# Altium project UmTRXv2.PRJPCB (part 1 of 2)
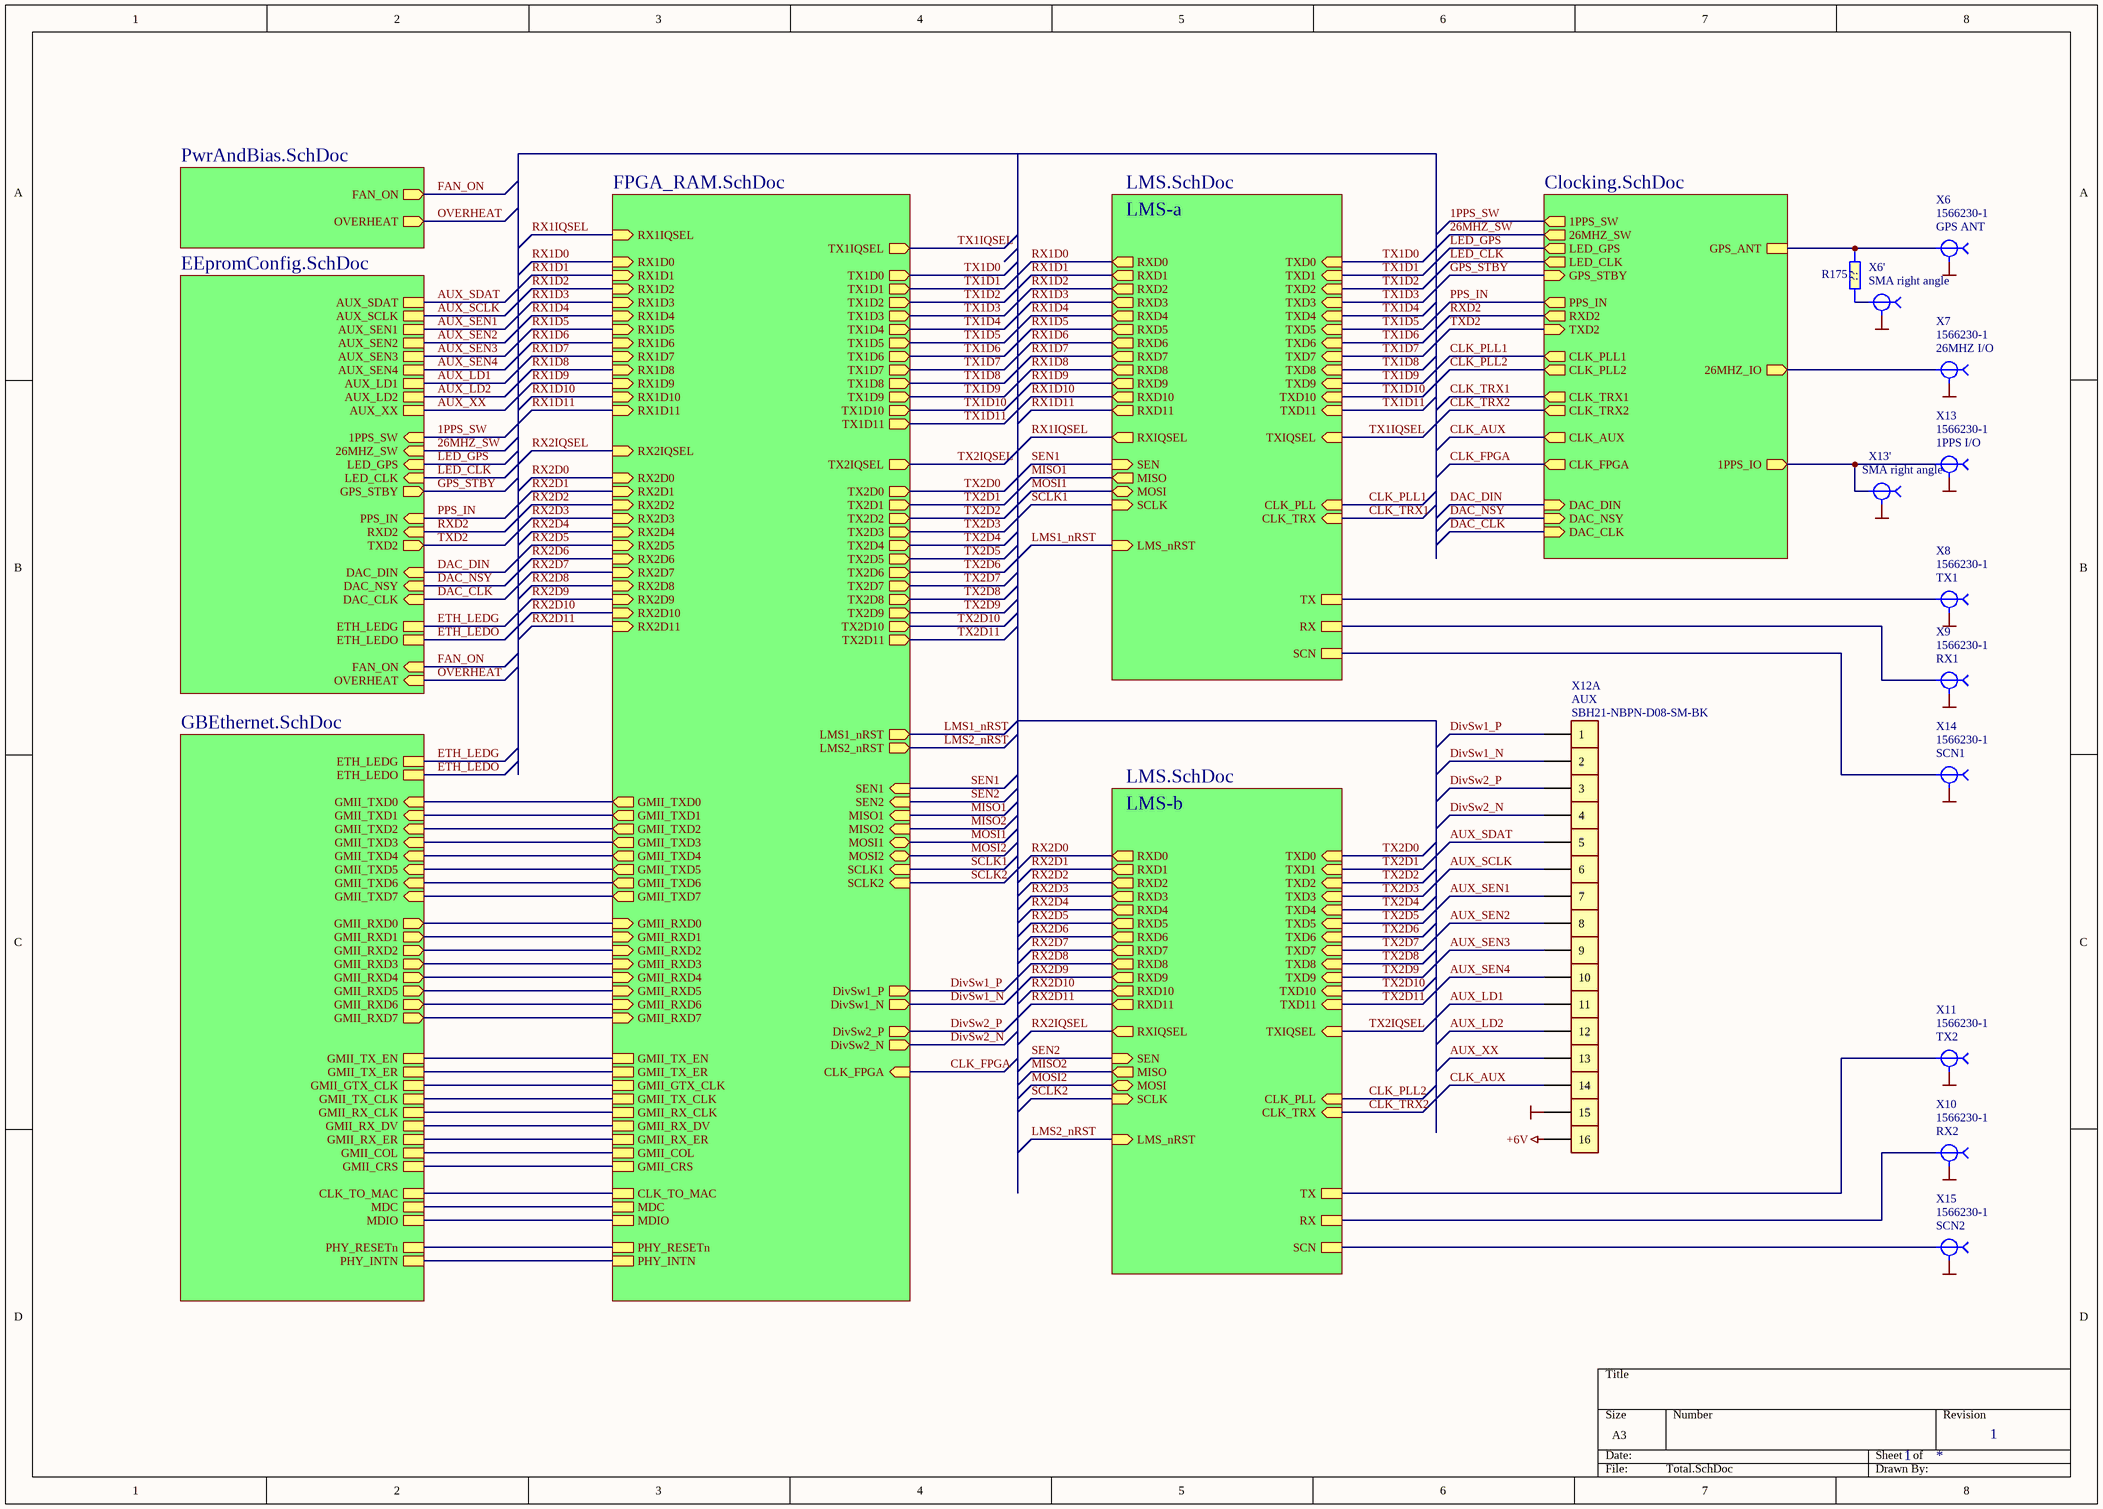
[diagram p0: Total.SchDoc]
7 sheets, 708 parts. Net scope: hierarchical (ports join the sheet entries above them; power ports are global).
Board file: UmTRXv2.PcbDoc
Sheets:
  Total.SchDoc
    PwrAndBias = PwrAndBias.SchDoc
    FPGA_RAM = FPGA_RAM.SchDoc
    GBEthernet = GBEthernet.SchDoc
    EEpromConfig = EEpromConfig.SchDoc
    Clocking = Clocking.SchDoc
    LMS-a = LMS.SchDoc
    LMS-b = LMS.SchDoc

## Sheet Total.SchDoc: USRP Cellular Tranceiver
size A3; Revision: 1; SheetNumber: 1

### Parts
R175  ??  [R0603-PHILLIPS]
X6  1566230-1  Dscription: GPS ANT  [U_FL]
X6'  SMA right angle  [SMA right angle]
X7  1566230-1  Dscription: 26MHZ I/O  [U_FL]
X8  1566230-1  Dscription: TX1  [U_FL]
X9  1566230-1  Dscription: RX1  [U_FL]
X10  1566230-1  Dscription: RX2  [U_FL]
X11  1566230-1  Dscription: TX2  [U_FL]
X12  SBH21-NBPN-D08-SM-BK  Misc: AUX  [SBH-16]  (parts A,B,C,D,E,F,G,H,I,J,K,L,M,N,O,P of 16)
X13  1566230-1  Dscription: 1PPS I/O  [U_FL]
X13'  SMA right angle  [SMA right angle]
X14  1566230-1  Dscription: SCN1  [U_FL]
X15  1566230-1  Dscription: SCN2  [U_FL]

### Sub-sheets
Clocking = Clocking.SchDoc: TXD2 (in), 26MHZ_IO (out), CLK_FPGA (out), CLK_TRX1 (out), GPS_ANT, DAC_DIN (in), DAC_NSY (in), DAC_CLK (in), PPS_IN (out), RXD2 (out), CLK_PLL1 (out), CLK_AUX (out), 1PPS_IO (out), CLK_PLL2 (out), CLK_TRX2 (out), 1PPS_SW (out), 26MHZ_SW (out), LED_GPS (out), LED_CLK (out), GPS_STBY (in)
EEpromConfig = EEpromConfig.SchDoc: PPS_IN (in), DAC_DIN (in), DAC_NSY (in), DAC_CLK (in), TXD2 (out), RXD2 (in), ETH_LEDG, ETH_LEDO, FAN_ON (in), OVERHEAT (in), AUX_SDAT, AUX_SCLK, AUX_SEN1, AUX_LD1, AUX_XX, AUX_SEN2, AUX_LD2, 1PPS_SW (in), 26MHZ_SW (in), LED_GPS (in), LED_CLK (in), AUX_SEN3, AUX_SEN4, GPS_STBY (out)
FPGA_RAM = FPGA_RAM.SchDoc: DivSw1_P (out), DivSw1_N (out), TX1IQSEL (out), TX2IQSEL (out), RX1IQSEL (in), RX2IQSEL (in), SEN1 (in), SEN2 (in), MISO1 (in), MOSI1 (bidir), SCLK1 (in), DivSw2_P (out), DivSw2_N (out), CLK_FPGA (in), CLK_TO_MAC, GMII_TX_EN, GMII_TX_ER, GMII_GTX_CLK, GMII_TX_CLK, GMII_RX_CLK, GMII_RX_DV, GMII_RX_ER, GMII_COL, GMII_CRS, MDIO, MDC, PHY_INTN, PHY_RESETn, MISO2 (in), MOSI2 (bidir), SCLK2 (in), LMS1_nRST (out), LMS2_nRST (out), TX1D0 (out), TX1D1 (out), TX1D2 (out), TX1D3 (out), TX1D4 (out), TX1D5 (out), TX1D6 (out), TX1D7 (out), TX1D8 (out), TX1D9 (out), TX1D10 (out), TX1D11 (out), TX2D0 (out), TX2D1 (out), TX2D2 (out), TX2D3 (out), TX2D4 (out), TX2D5 (out), TX2D6 (out), TX2D7 (out), TX2D8 (out), TX2D9 (out), TX2D10 (out), TX2D11 (out), RX1D0 (in), RX1D1 (in), RX1D2 (in), RX1D3 (in), RX1D4 (in), RX1D5 (in), RX1D6 (in), RX1D7 (in), RX1D8 (in), RX1D9 (in), RX1D10 (in), RX1D11 (in), RX2D0 (in), RX2D1 (in), RX2D2 (in), RX2D3 (in), RX2D4 (in), RX2D5 (in), RX2D6 (in), RX2D7 (in), RX2D8 (in), RX2D9 (in), RX2D10 (in), RX2D11 (in), GMII_TXD0 (out), GMII_TXD1 (out), GMII_TXD2 (out), GMII_TXD3 (out), GMII_TXD4 (out), GMII_TXD5 (out), GMII_TXD6 (out), GMII_TXD7 (out), GMII_RXD0 (in), GMII_RXD1 (in), GMII_RXD2 (in), GMII_RXD3 (in), GMII_RXD4 (in), GMII_RXD5 (in), GMII_RXD6 (in), GMII_RXD7 (in)
GBEthernet = GBEthernet.SchDoc: CLK_TO_MAC, GMII_TX_ER, GMII_TX_EN, GMII_GTX_CLK, GMII_RX_CLK, GMII_TX_CLK, GMII_RX_DV, GMII_RX_ER, GMII_COL, GMII_CRS, MDC, MDIO, PHY_INTN, PHY_RESETn, ETH_LEDG, GMII_TXD0 (in), GMII_TXD1 (in), GMII_TXD2 (in), GMII_TXD3 (in), GMII_TXD4 (in), GMII_TXD5 (in), GMII_TXD6 (in), GMII_TXD7 (in), GMII_RXD0 (out), GMII_RXD1 (out), GMII_RXD2 (out), GMII_RXD3 (out), GMII_RXD4 (out), GMII_RXD5 (out), GMII_RXD6 (out), GMII_RXD7 (out), ETH_LEDO
LMS-a = LMS.SchDoc: RXD0 (out), RXIQSEL (out), SEN (in), MISO (out), MOSI (bidir), SCLK (in), RXD1 (out), RXD2 (out), RXD3 (out), RXD4 (out), RXD5 (out), RXD6 (out), RXD7 (out), RXD8 (out), RXD9 (out), RXD10 (out), RXD11 (out), TXD0 (in), TXIQSEL (in), CLK_PLL (in), TXD1 (in), TXD2 (in), TXD3 (in), TXD4 (in), TXD5 (in), TXD6 (in), TXD7 (in), TXD8 (in), TXD9 (in), TXD10 (in), TXD11 (in), TX, RX, LMS_nRST (in), SCN, CLK_TRX (in)
LMS-b = LMS.SchDoc: RXD0 (out), RXIQSEL (out), SEN (in), MISO (out), MOSI (bidir), SCLK (in), RXD1 (out), RXD2 (out), RXD3 (out), RXD4 (out), RXD5 (out), RXD6 (out), RXD7 (out), RXD8 (out), RXD9 (out), RXD10 (out), RXD11 (out), TXD0 (in), TXIQSEL (in), CLK_PLL (in), TXD1 (in), TXD2 (in), TXD3 (in), TXD4 (in), TXD5 (in), TXD6 (in), TXD7 (in), TXD8 (in), TXD9 (in), TXD10 (in), TXD11 (in), TX, RX, LMS_nRST (in), CLK_TRX (in), SCN
PwrAndBias = PwrAndBias.SchDoc: FAN_ON (out), OVERHEAT (out)

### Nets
+6V: X12.16
GND: X6.2(GND) X6'.2(GND) X7.2(GND) X8.2(GND) X9.2(GND) X10.2(GND) X11.2(GND) X12.15 X13.2(GND) X13'.2(GND) X14.2(GND) X15.2(GND)
1PPS_IO: X13.1 X13'.1 ; sheet Clocking/1PPS_IO
1PPS_SW: sheet EEpromConfig/1PPS_SW, sheet Clocking/1PPS_SW
26MHZ_IO: X7.1 ; sheet Clocking/26MHZ_IO
26MHZ_SW: sheet EEpromConfig/26MHZ_SW, sheet Clocking/26MHZ_SW
AUX_LD1: X12.11 ; sheet EEpromConfig/AUX_LD1
AUX_LD2: X12.12 ; sheet EEpromConfig/AUX_LD2
AUX_SCLK: X12.6 ; sheet EEpromConfig/AUX_SCLK
AUX_SDAT: X12.5 ; sheet EEpromConfig/AUX_SDAT
AUX_SEN1: X12.7 ; sheet EEpromConfig/AUX_SEN1
AUX_SEN2: X12.8 ; sheet EEpromConfig/AUX_SEN2
AUX_SEN3: X12.9 ; sheet EEpromConfig/AUX_SEN3
AUX_SEN4: X12.10 ; sheet EEpromConfig/AUX_SEN4
AUX_XX: X12.13 ; sheet EEpromConfig/AUX_XX
CLK_AUX: X12.14 ; sheet Clocking/CLK_AUX
CLK_FPGA: sheet FPGA_RAM/CLK_FPGA, sheet Clocking/CLK_FPGA
CLK_PLL1: sheet Clocking/CLK_PLL1, sheet LMS-a/CLK_PLL
CLK_PLL2: sheet Clocking/CLK_PLL2, sheet LMS-b/CLK_PLL
CLK_TO_MAC: sheet FPGA_RAM/CLK_TO_MAC, sheet GBEthernet/CLK_TO_MAC
CLK_TRX1: sheet Clocking/CLK_TRX1, sheet LMS-a/CLK_TRX
CLK_TRX2: sheet Clocking/CLK_TRX2, sheet LMS-b/CLK_TRX
DAC_CLK: sheet EEpromConfig/DAC_CLK, sheet Clocking/DAC_CLK
DAC_DIN: sheet EEpromConfig/DAC_DIN, sheet Clocking/DAC_DIN
DAC_NSY: sheet EEpromConfig/DAC_NSY, sheet Clocking/DAC_NSY
DivSw1_N: X12.2 ; sheet FPGA_RAM/DivSw1_N
DivSw1_P: X12.1 ; sheet FPGA_RAM/DivSw1_P
DivSw2_N: X12.4 ; sheet FPGA_RAM/DivSw2_N
DivSw2_P: X12.3 ; sheet FPGA_RAM/DivSw2_P
ETH_LEDG: sheet GBEthernet/ETH_LEDG, sheet EEpromConfig/ETH_LEDG
ETH_LEDO: sheet GBEthernet/ETH_LEDO, sheet EEpromConfig/ETH_LEDO
FAN_ON: sheet PwrAndBias/FAN_ON, sheet EEpromConfig/FAN_ON
GMII_COL: sheet FPGA_RAM/GMII_COL, sheet GBEthernet/GMII_COL
GMII_CRS: sheet FPGA_RAM/GMII_CRS, sheet GBEthernet/GMII_CRS
GMII_GTX_CLK: sheet FPGA_RAM/GMII_GTX_CLK, sheet GBEthernet/GMII_GTX_CLK
GMII_RX_CLK: sheet FPGA_RAM/GMII_RX_CLK, sheet GBEthernet/GMII_RX_CLK
GMII_RX_DV: sheet FPGA_RAM/GMII_RX_DV, sheet GBEthernet/GMII_RX_DV
GMII_RX_ER: sheet FPGA_RAM/GMII_RX_ER, sheet GBEthernet/GMII_RX_ER
GMII_RXD0: sheet FPGA_RAM/GMII_RXD0, sheet GBEthernet/GMII_RXD0
GMII_RXD1: sheet FPGA_RAM/GMII_RXD1, sheet GBEthernet/GMII_RXD1
GMII_RXD2: sheet FPGA_RAM/GMII_RXD2, sheet GBEthernet/GMII_RXD2
GMII_RXD3: sheet FPGA_RAM/GMII_RXD3, sheet GBEthernet/GMII_RXD3
GMII_RXD4: sheet FPGA_RAM/GMII_RXD4, sheet GBEthernet/GMII_RXD4
GMII_RXD5: sheet FPGA_RAM/GMII_RXD5, sheet GBEthernet/GMII_RXD5
GMII_RXD6: sheet FPGA_RAM/GMII_RXD6, sheet GBEthernet/GMII_RXD6
GMII_RXD7: sheet FPGA_RAM/GMII_RXD7, sheet GBEthernet/GMII_RXD7
GMII_TX_CLK: sheet FPGA_RAM/GMII_TX_CLK, sheet GBEthernet/GMII_TX_CLK
GMII_TX_EN: sheet FPGA_RAM/GMII_TX_EN, sheet GBEthernet/GMII_TX_EN
GMII_TX_ER: sheet FPGA_RAM/GMII_TX_ER, sheet GBEthernet/GMII_TX_ER
GMII_TXD0: sheet FPGA_RAM/GMII_TXD0, sheet GBEthernet/GMII_TXD0
GMII_TXD1: sheet FPGA_RAM/GMII_TXD1, sheet GBEthernet/GMII_TXD1
GMII_TXD2: sheet FPGA_RAM/GMII_TXD2, sheet GBEthernet/GMII_TXD2
GMII_TXD3: sheet FPGA_RAM/GMII_TXD3, sheet GBEthernet/GMII_TXD3
GMII_TXD4: sheet FPGA_RAM/GMII_TXD4, sheet GBEthernet/GMII_TXD4
GMII_TXD5: sheet FPGA_RAM/GMII_TXD5, sheet GBEthernet/GMII_TXD5
GMII_TXD6: sheet FPGA_RAM/GMII_TXD6, sheet GBEthernet/GMII_TXD6
GMII_TXD7: sheet FPGA_RAM/GMII_TXD7, sheet GBEthernet/GMII_TXD7
GPS_ANT: R175.2 X6.1 ; sheet Clocking/GPS_ANT
GPS_STBY: sheet EEpromConfig/GPS_STBY, sheet Clocking/GPS_STBY
LED_CLK: sheet EEpromConfig/LED_CLK, sheet Clocking/LED_CLK
LED_GPS: sheet EEpromConfig/LED_GPS, sheet Clocking/LED_GPS
LMS1_nRST: sheet FPGA_RAM/LMS1_nRST, sheet LMS-a/LMS_nRST
LMS2_nRST: sheet FPGA_RAM/LMS2_nRST, sheet LMS-b/LMS_nRST
MDC: sheet FPGA_RAM/MDC, sheet GBEthernet/MDC
MDIO: sheet FPGA_RAM/MDIO, sheet GBEthernet/MDIO
MISO1: sheet FPGA_RAM/MISO1, sheet LMS-a/MISO
MISO2: sheet FPGA_RAM/MISO2, sheet LMS-b/MISO
MOSI1: sheet FPGA_RAM/MOSI1, sheet LMS-a/MOSI
MOSI2: sheet FPGA_RAM/MOSI2, sheet LMS-b/MOSI
OVERHEAT: sheet PwrAndBias/OVERHEAT, sheet EEpromConfig/OVERHEAT
PHY_INTN: sheet FPGA_RAM/PHY_INTN, sheet GBEthernet/PHY_INTN
PHY_RESETn: sheet FPGA_RAM/PHY_RESETn, sheet GBEthernet/PHY_RESETn
PPS_IN: sheet EEpromConfig/PPS_IN, sheet Clocking/PPS_IN
RX: X9.1 ; sheet LMS-a/RX
RX: X10.1 ; sheet LMS-b/RX  [a separate net that carries the same name]
RX1D0: sheet FPGA_RAM/RX1D0, sheet LMS-a/RXD0
RX1D1: sheet FPGA_RAM/RX1D1, sheet LMS-a/RXD1
RX1D2: sheet FPGA_RAM/RX1D2, sheet LMS-a/RXD2
RX1D3: sheet FPGA_RAM/RX1D3, sheet LMS-a/RXD3
RX1D4: sheet FPGA_RAM/RX1D4, sheet LMS-a/RXD4
RX1D5: sheet FPGA_RAM/RX1D5, sheet LMS-a/RXD5
RX1D6: sheet FPGA_RAM/RX1D6, sheet LMS-a/RXD6
RX1D7: sheet FPGA_RAM/RX1D7, sheet LMS-a/RXD7
RX1D8: sheet FPGA_RAM/RX1D8, sheet LMS-a/RXD8
RX1D9: sheet FPGA_RAM/RX1D9, sheet LMS-a/RXD9
RX1D10: sheet FPGA_RAM/RX1D10, sheet LMS-a/RXD10
RX1D11: sheet FPGA_RAM/RX1D11, sheet LMS-a/RXD11
RX1IQSEL: sheet FPGA_RAM/RX1IQSEL, sheet LMS-a/RXIQSEL
RX2D0: sheet FPGA_RAM/RX2D0, sheet LMS-b/RXD0
RX2D1: sheet FPGA_RAM/RX2D1, sheet LMS-b/RXD1
RX2D2: sheet FPGA_RAM/RX2D2, sheet LMS-b/RXD2
RX2D3: sheet FPGA_RAM/RX2D3, sheet LMS-b/RXD3
RX2D4: sheet FPGA_RAM/RX2D4, sheet LMS-b/RXD4
RX2D5: sheet FPGA_RAM/RX2D5, sheet LMS-b/RXD5
RX2D6: sheet FPGA_RAM/RX2D6, sheet LMS-b/RXD6
RX2D7: sheet FPGA_RAM/RX2D7, sheet LMS-b/RXD7
RX2D8: sheet FPGA_RAM/RX2D8, sheet LMS-b/RXD8
RX2D9: sheet FPGA_RAM/RX2D9, sheet LMS-b/RXD9
RX2D10: sheet FPGA_RAM/RX2D10, sheet LMS-b/RXD10
RX2D11: sheet FPGA_RAM/RX2D11, sheet LMS-b/RXD11
RX2IQSEL: sheet FPGA_RAM/RX2IQSEL, sheet LMS-b/RXIQSEL
RXD2: sheet EEpromConfig/RXD2, sheet Clocking/RXD2
SCLK1: sheet FPGA_RAM/SCLK1, sheet LMS-a/SCLK
SCLK2: sheet FPGA_RAM/SCLK2, sheet LMS-b/SCLK
SCN: X14.1 ; sheet LMS-a/SCN
SCN: X15.1 ; sheet LMS-b/SCN  [a separate net that carries the same name]
SEN1: sheet FPGA_RAM/SEN1, sheet LMS-a/SEN
SEN2: sheet FPGA_RAM/SEN2, sheet LMS-b/SEN
TX: X8.1 ; sheet LMS-a/TX
TX: X11.1 ; sheet LMS-b/TX  [a separate net that carries the same name]
TX1D0: sheet FPGA_RAM/TX1D0, sheet LMS-a/TXD0
TX1D1: sheet FPGA_RAM/TX1D1, sheet LMS-a/TXD1
TX1D2: sheet FPGA_RAM/TX1D2, sheet LMS-a/TXD2
TX1D3: sheet FPGA_RAM/TX1D3, sheet LMS-a/TXD3
TX1D4: sheet FPGA_RAM/TX1D4, sheet LMS-a/TXD4
TX1D5: sheet FPGA_RAM/TX1D5, sheet LMS-a/TXD5
TX1D6: sheet FPGA_RAM/TX1D6, sheet LMS-a/TXD6
TX1D7: sheet FPGA_RAM/TX1D7, sheet LMS-a/TXD7
TX1D8: sheet FPGA_RAM/TX1D8, sheet LMS-a/TXD8
TX1D9: sheet FPGA_RAM/TX1D9, sheet LMS-a/TXD9
TX1D10: sheet FPGA_RAM/TX1D10, sheet LMS-a/TXD10
TX1D11: sheet FPGA_RAM/TX1D11, sheet LMS-a/TXD11
TX1IQSEL: sheet FPGA_RAM/TX1IQSEL, sheet LMS-a/TXIQSEL
TX2D0: sheet FPGA_RAM/TX2D0, sheet LMS-b/TXD0
TX2D1: sheet FPGA_RAM/TX2D1, sheet LMS-b/TXD1
TX2D2: sheet FPGA_RAM/TX2D2, sheet LMS-b/TXD2
TX2D3: sheet FPGA_RAM/TX2D3, sheet LMS-b/TXD3
TX2D4: sheet FPGA_RAM/TX2D4, sheet LMS-b/TXD4
TX2D5: sheet FPGA_RAM/TX2D5, sheet LMS-b/TXD5
TX2D6: sheet FPGA_RAM/TX2D6, sheet LMS-b/TXD6
TX2D7: sheet FPGA_RAM/TX2D7, sheet LMS-b/TXD7
TX2D8: sheet FPGA_RAM/TX2D8, sheet LMS-b/TXD8
TX2D9: sheet FPGA_RAM/TX2D9, sheet LMS-b/TXD9
TX2D10: sheet FPGA_RAM/TX2D10, sheet LMS-b/TXD10
TX2D11: sheet FPGA_RAM/TX2D11, sheet LMS-b/TXD11
TX2IQSEL: sheet FPGA_RAM/TX2IQSEL, sheet LMS-b/TXIQSEL
TXD2: sheet EEpromConfig/TXD2, sheet Clocking/TXD2
NetR175_1: R175.1 X6'.1

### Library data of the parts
R175 = R0603: Резистор; Manufacturer: YAGEO; Tolerance: 5%; Name: SMD0603; U/P/TKE: 0.1W
X6-X11 X13-X15 = U_FL: Ultraminiature Coax Connector (UMCC); Manufacturer: Tyco Electronics Corp
X6' X13' = SMA-Right Angle: Разъем
X12 = SBH21-8x2_SMD: Connector 2mm SMD; Manufacturer: Sullins

## Sheet PwrAndBias.SchDoc: Pwr And Biasing
size A3; Revision: 1; SheetNumber: 9
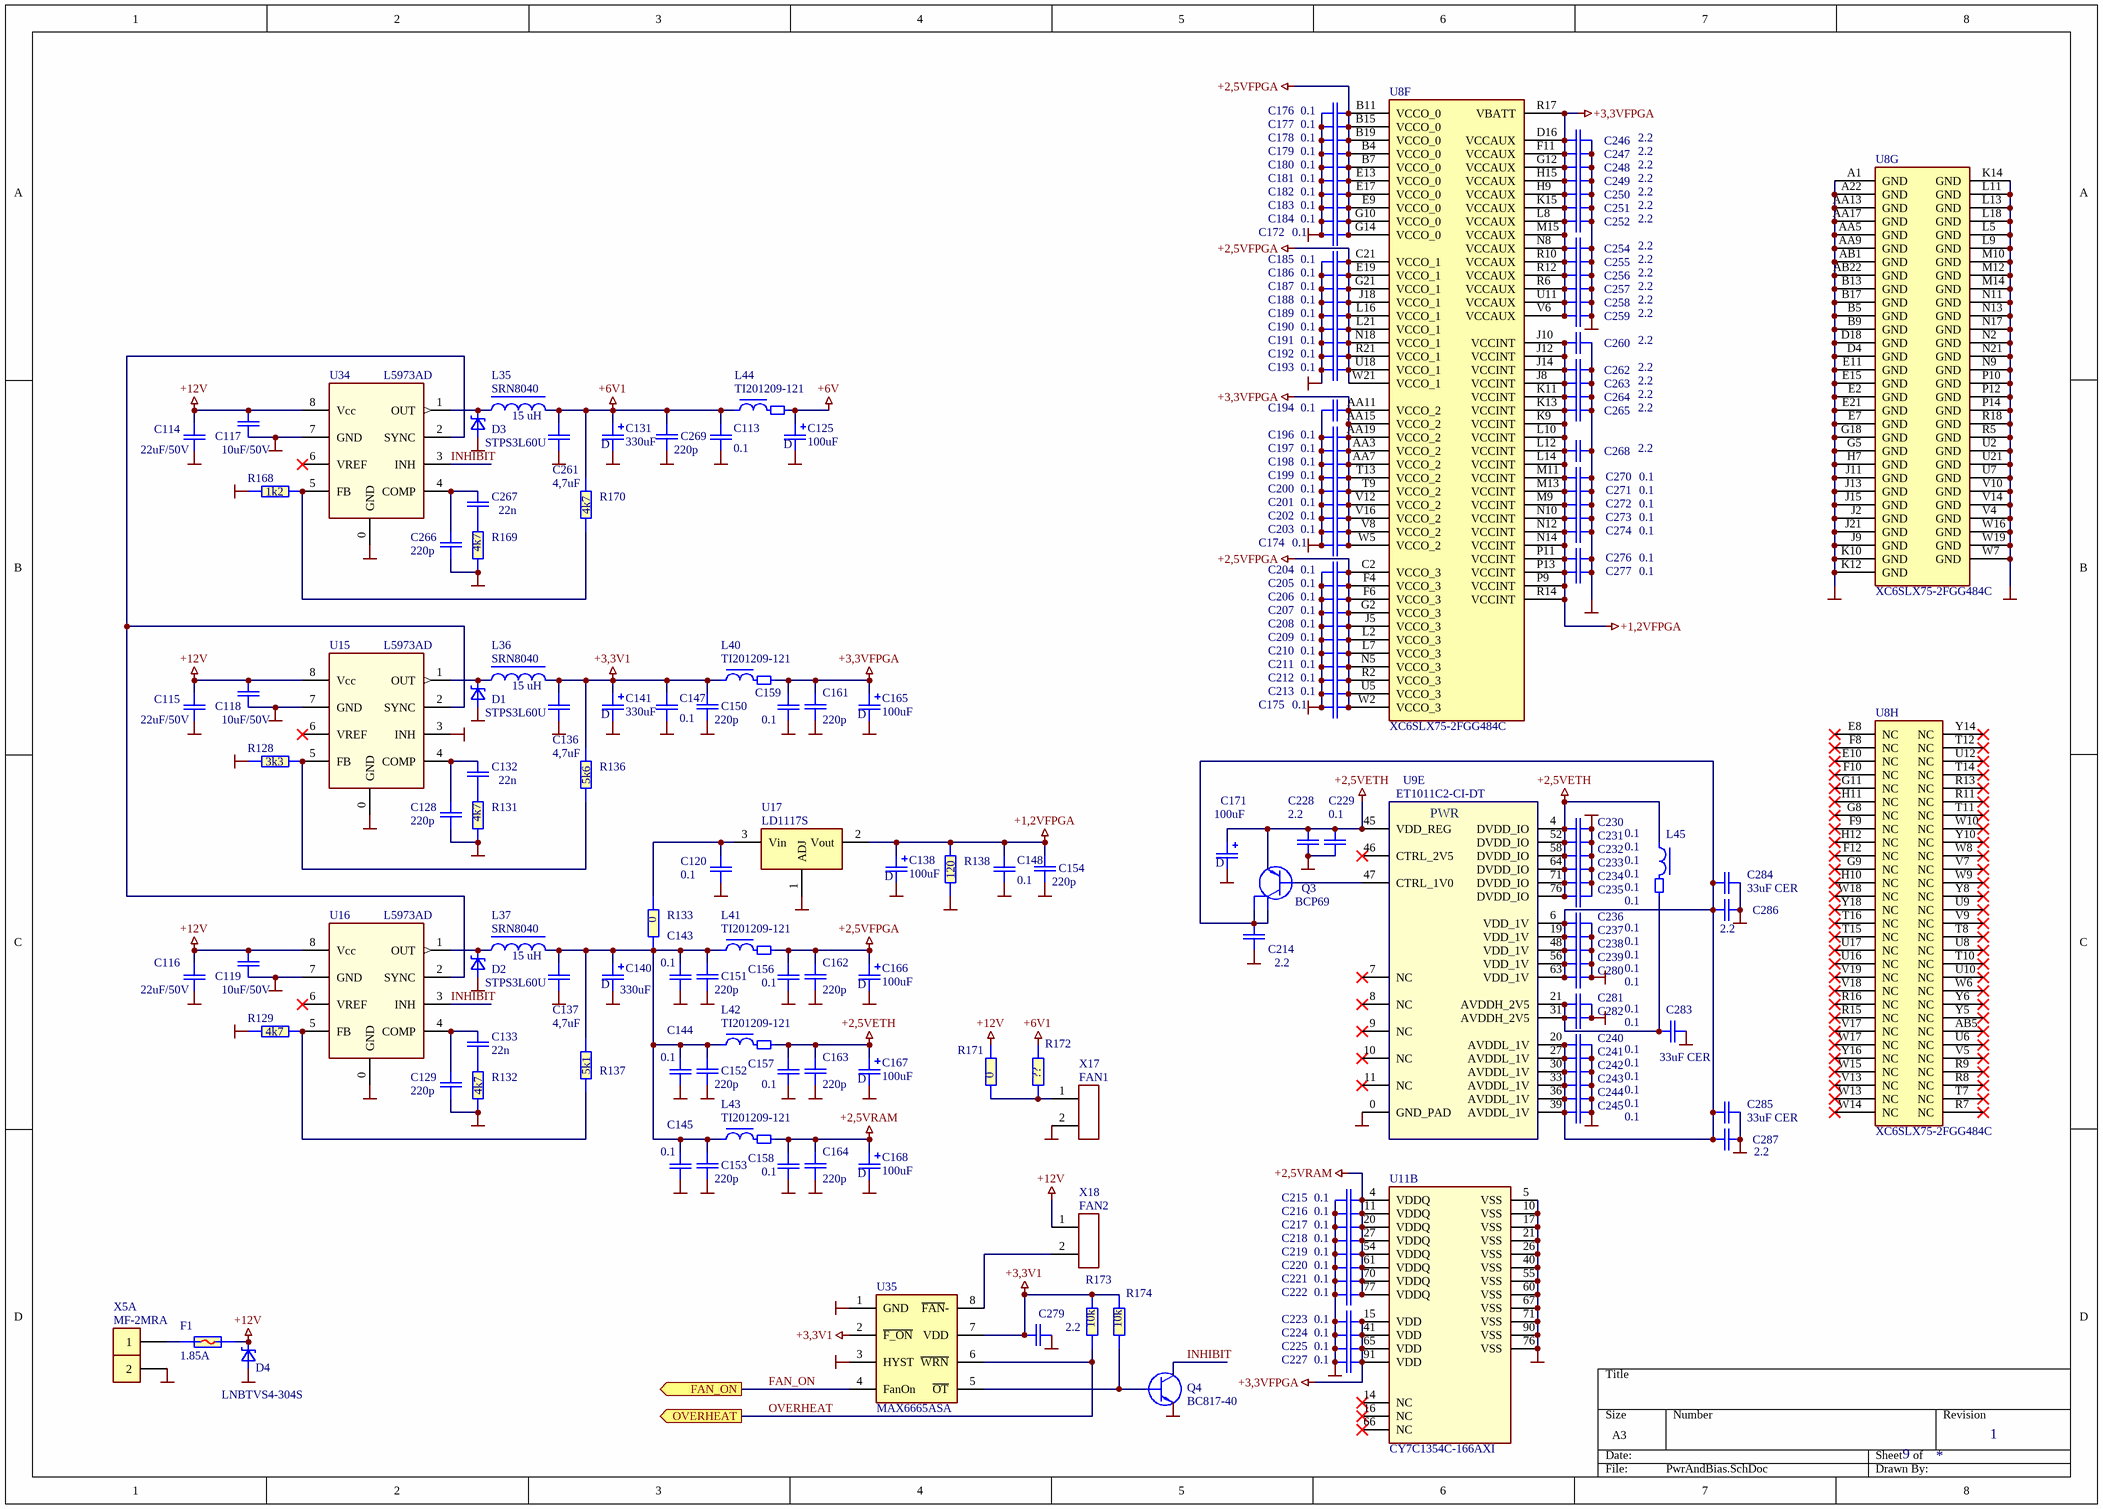
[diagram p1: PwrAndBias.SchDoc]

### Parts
C113  0.1  [C0402-Phillips]
C114  22uF/50V  [C2220]
C115  22uF/50V  [C2220]
C116  22uF/50V  [C2220]
C117  10uF/50V  [C1210_H2,5]
C118  10uF/50V  [C1210_H2,5]
C119  10uF/50V  [C1210_H2,5]
C120  0.1  [C0402-Phillips]
C125  100uF  [cd7343]
C128  220p  [C0603-PHILLIPS]
C129  220p  [C0603-PHILLIPS]
C131  330uF  [cd7343]
C132  22n  [C0603-PHILLIPS]
C133  22n  [C0603-PHILLIPS]
C136  4,7uF  [c1206]
C137  4,7uF  [c1206]
C138  100uF  [cd7343]
C140  330uF  [cd7343]
C141  330uF  [cd7343]
C143  0.1  [C0402-Phillips]
C144  0.1  [C0402-Phillips]
C145  0.1  [C0402-Phillips]
C147  0.1  [C0402-Phillips]
C148  0.1  [C0402-Phillips]
C150  220p  [C0603-PHILLIPS]
C151  220p  [C0603-PHILLIPS]
C152  220p  [C0603-PHILLIPS]
C153  220p  [C0603-PHILLIPS]
C154  220p  [C0603-PHILLIPS]
C156  0.1  [C0402-Phillips]
C157  0.1  [C0402-Phillips]
C158  0.1  [C0402-Phillips]
C159  0.1  [C0402-Phillips]
C161  220p  [C0603-PHILLIPS]
C162  220p  [C0603-PHILLIPS]
C163  220p  [C0603-PHILLIPS]
C164  220p  [C0603-PHILLIPS]
C165  100uF  [cd7343]
C166  100uF  [cd7343]
C167  100uF  [cd7343]
C168  100uF  [cd7343]
C171  100uF  [cd7343]
C172  0.1  [C0402-cirq]
C174  0.1  [C0402-cirq]
C175  0.1  [C0402-cirq]
C176  0.1  [C0402-cirq]
C177  0.1  [C0402-cirq]
C178  0.1  [C0402-cirq]
C179  0.1  [C0402-cirq]
C180  0.1  [C0402-cirq]
C181  0.1  [C0402-cirq]
C182  0.1  [C0402-cirq]
C183  0.1  [C0402-cirq]
C184  0.1  [C0402-cirq]
C185  0.1  [C0402-cirq]
C186  0.1  [C0402-cirq]
C187  0.1  [C0402-cirq]
C188  0.1  [C0402-cirq]
C189  0.1  [C0402-cirq]
C190  0.1  [C0402-cirq]
C191  0.1  [C0402-cirq]
C192  0.1  [C0402-cirq]
C193  0.1  [C0402-cirq]
C194  0.1  [C0402-cirq]
C196  0.1  [C0402-cirq]
C197  0.1  [C0402-cirq]
C198  0.1  [C0402-cirq]
C199  0.1  [C0402-cirq]
C200  0.1  [C0402-cirq]
C201  0.1  [C0402-cirq]
C202  0.1  [C0402-cirq]
C203  0.1  [C0402-cirq]
C204  0.1  [C0402-cirq]
C205  0.1  [C0402-cirq]
C206  0.1  [C0402-cirq]
C207  0.1  [C0402-cirq]
C208  0.1  [C0402-cirq]
C209  0.1  [C0402-cirq]
C210  0.1  [C0402-cirq]
C211  0.1  [C0402-cirq]
C212  0.1  [C0402-cirq]
C213  0.1  [C0402-cirq]
C214  2.2  [C0402-Phillips]
C215  0.1  [C0402-Phillips]
C216  0.1  [C0402-Phillips]
C217  0.1  [C0402-Phillips]
C218  0.1  [C0402-Phillips]
C219  0.1  [C0402-Phillips]
C220  0.1  [C0402-Phillips]
C221  0.1  [C0402-Phillips]
C222  0.1  [C0402-Phillips]
C223  0.1  [C0402-Phillips]
C224  0.1  [C0402-Phillips]
C225  0.1  [C0402-Phillips]
C227  0.1  [C0402-Phillips]
C228  2.2  [C0402-Phillips]
C229  0.1  [C0402-Phillips]
C230  0.1  [C0402-Phillips]
C231  0.1  [C0402-Phillips]
C232  0.1  [C0402-Phillips]
C233  0.1  [C0402-Phillips]
C234  0.1  [C0402-Phillips]
C235  0.1  [C0402-Phillips]
C236  0.1  [C0402-Phillips]
C237  0.1  [C0402-Phillips]
C238  0.1  [C0402-Phillips]
C239  0.1  [C0402-Phillips]
C240  0.1  [C0402-Phillips]
C241  0.1  [C0402-Phillips]
C242  0.1  [C0402-Phillips]
C243  0.1  [C0402-Phillips]
C244  0.1  [C0402-Phillips]
C245  0.1  [C0402-Phillips]
C246  2.2  [C0402-cirq]
C247  2.2  [C0402-cirq]
C248  2.2  [C0402-cirq]
C249  2.2  [C0402-cirq]
C250  2.2  [C0402-cirq]
C251  2.2  [C0402-cirq]
C252  2.2  [C0402-cirq]
C254  2.2  [C0402-cirq]
C255  2.2  [C0402-cirq]
C256  2.2  [C0402-cirq]
C257  2.2  [C0402-cirq]
C258  2.2  [C0402-cirq]
C259  2.2  [C0402-cirq]
C260  2.2  [C0402-cirq]
C261  4,7uF  [c1206]
C262  2.2  [C0402-cirq]
C263  2.2  [C0402-cirq]
C264  2.2  [C0402-cirq]
C265  2.2  [C0402-cirq]
C266  220p  [C0603-PHILLIPS]
C267  22n  [C0603-PHILLIPS]
C268  2.2  [C0402-cirq]
C269  220p  [C0603-PHILLIPS]
C270  0.1  [C0402-cirq]
C271  0.1  [C0402-cirq]
C272  0.1  [C0402-cirq]
C273  0.1  [C0402-cirq]
C274  0.1  [C0402-cirq]
C276  0.1  [C0402-cirq]
C277  0.1  [C0402-cirq]
C279  2.2  [C0402-Phillips]
C280  0.1  [C0402-Phillips]
C281  0.1  [C0402-Phillips]
C282  0.1  [C0402-Phillips]
C283  33uF CER  [C0805-Phillips]
C284  33uF CER  [C0805-Phillips]
C285  33uF CER  [C0805-Phillips]
C286  2.2  [C0402-Phillips]
C287  2.2  [C0402-Phillips]
D1  STPS3L60U  [SMB]
D2  STPS3L60U  [SMB]
D3  STPS3L60U  [SMB]
D4  LNBTVS4-304S  [SMC]
F1  1.85A  [FUSE2920]
L35  15 uH  [SRN8040]
L36  15 uH  [SRN8040]
L37  15 uH  [SRN8040]
L40  TI201209-121  [TI2012-Phillips]
L41  TI201209-121  [TI2012-Phillips]
L42  TI201209-121  [TI2012-Phillips]
L43  TI201209-121  [TI2012-Phillips]
L44  TI201209-121  [TI2012-Phillips]
L45  TI160808U601  [Ti160808-Phillips]  (value not drawn)
Q3  BCP69  [SOT-223]
Q4  BC817-40  [SOT23-Philips]
R128  3k3  [R0603-PHILLIPS]
R129  4k7  [R0603-PHILLIPS]
R131  4k7  [R0603-PHILLIPS]
R132  4k7  [R0603-PHILLIPS]
R133  0  [R0603-PHILLIPS]
R136  5k6  [R0603-PHILLIPS]
R137  5k1  [R0603-PHILLIPS]
R138  120  [R0603-PHILLIPS]
R168  1k2  [R0603-PHILLIPS]
R169  4k7  [R0603-PHILLIPS]
R170  4k7  [R0603-PHILLIPS]
R171  0  [R0603-PHILLIPS]
R172  ??  [R0603-PHILLIPS]
R173  10k  [R0603-PHILLIPS]
R174  10k  [R0603-PHILLIPS]
U8  XC6SLX75-2FGG484C  [FBGA484]  (parts F,G,H of 8)
U9  ET1011C2-CI-DT  [QFN-84(10x10/0/4mm)with_pad]  (part E of 5)
U11  CY7C1354C-166AXI  [QFP-10020X14/0.65]]  (part B of 2)
U15  L5973AD  [SOIC8 - BackGND - 0.4mm dia]
U16  L5973AD  [SOIC8 - BackGND - 0.4mm dia]
U17  LD1117S  [SOT-223-1]
U34  L5973AD  [SOIC8 - BackGND - 0.4mm dia]
U35  MAX6665ASA  [SO-8]
X5  MF-2MRA  [MF-2MRA]  (parts A,B of 2)
X17  FAN1  [WF-2]
X18  FAN2  [WF-2]

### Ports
FAN_ON (out), OVERHEAT (out)

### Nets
+1,2VFPGA: C138.1(+) C148.1 C154.1 C260.1 C262.1 C263.1 C264.1 C265.1 C268.1 C270.1 C271.1 C272.1 C273.1 C274.1 C276.1 C277.1 R138.1 U8.J8(VCCINT) U8.J10(VCCINT) U8.J12(VCCINT) U8.J14(VCCINT) U8.K9(VCCINT) U8.K11(VCCINT) U8.K13(VCCINT) U8.L10(VCCINT) U8.L12(VCCINT) U8.L14(VCCINT) U8.M9(VCCINT) U8.M11(VCCINT) U8.M13(VCCINT) U8.N10(VCCINT) U8.N12(VCCINT) U8.N14(VCCINT) U8.P9(VCCINT) U8.P11(VCCINT) U8.P13(VCCINT) U8.R14(VCCINT) U17.2(Vout)
+2,5VETH: C157.1 C163.1 C167.1(+) C171.1(+) C228.2 C229.1 C230.1 C231.1 C232.1 C233.1 C234.1 C235.1 L42.2 L45.1 Q3.3(E) U9.4(DVDD_IO) U9.45(VDD_REG) U9.52(DVDD_IO) U9.58(DVDD_IO) U9.64(DVDD_IO) U9.71(DVDD_IO) U9.76(DVDD_IO)
+2,5VFPGA: C156.1 C162.1 C166.1(+) C172.2 C175.2 C176.2 C177.2 C178.2 C179.2 C180.2 C181.2 C182.2 C183.2 C184.2 C185.2 C186.2 C187.2 C188.2 C189.2 C190.2 C191.2 C192.2 C193.2 C204.2 C205.2 C206.2 C207.2 C208.2 C209.2 C210.2 C211.2 C212.2 C213.2 L41.2 U8.B4(VCCO_0) U8.B7(VCCO_0) U8.B11(VCCO_0) U8.B15(VCCO_0) U8.B19(VCCO_0) U8.C2(VCCO_3) U8.C21(VCCO_1) U8.E9(VCCO_0) U8.E13(VCCO_0) U8.E17(VCCO_0) U8.E19(VCCO_1) U8.F4(VCCO_3) U8.F6(VCCO_3) U8.G2(VCCO_3) U8.G10(VCCO_0) U8.G14(VCCO_0) U8.G21(VCCO_1) U8.J5(VCCO_3) U8.J18(VCCO_1) U8.L2(VCCO_3) U8.L7(VCCO_3) U8.L16(VCCO_1) U8.L21(VCCO_1) U8.N5(VCCO_3) U8.N18(VCCO_1) U8.R2(VCCO_3) U8.R21(VCCO_1) U8.U5(VCCO_3) U8.U18(VCCO_1) U8.W2(VCCO_3) U8.W21(VCCO_1)
+2,5VRAM: C158.1 C164.1 C168.1(+) C215.2 C216.2 C217.2 C218.2 C219.2 C220.2 C221.2 C222.2 L43.2 U11.4(VDDQ) U11.11(VDDQ) U11.20(VDDQ) U11.27(VDDQ) U11.54(VDDQ) U11.61(VDDQ) U11.70(VDDQ) U11.77(VDDQ)
+3,3V1: C136.1 C141.1(+) C147.1 C150.1 C279.1 L36.2 L40.1 R136.1 R173.1 R174.1 U35.2(~{F_ON}) U35.7(VDD)
+3,3VFPGA: C159.1 C161.1 C165.1(+) C174.2 C194.2 C196.2 C197.2 C198.2 C199.2 C200.2 C201.2 C202.2 C203.2 C223.2 C224.2 C225.2 C227.2 C246.1 C247.1 C248.1 C249.1 C250.1 C251.1 C252.1 C254.1 C255.1 C256.1 C257.1 C258.1 C259.1 L40.2 U8.AA3(VCCO_2) U8.AA7(VCCO_2) U8.AA11(VCCO_2) U8.AA15(VCCO_2) U8.AA19(VCCO_2) U8.D16(VCCAUX) U8.F11(VCCAUX) U8.G12(VCCAUX) U8.H9(VCCAUX) U8.H15(VCCAUX) U8.K15(VCCAUX) U8.L8(VCCAUX) U8.M15(VCCAUX) U8.N8(VCCAUX) U8.R6(VCCAUX) U8.R10(VCCAUX) U8.R12(VCCAUX) U8.R17(VBATT) U8.T9(VCCO_2) U8.T13(VCCO_2) U8.U11(VCCAUX) U8.V6(VCCAUX) U8.V8(VCCO_2) U8.V12(VCCO_2) U8.V16(VCCO_2) U8.W5(VCCO_2) U11.15(VDD) U11.41(VDD) U11.65(VDD) U11.91(VDD)
+6V: C125.1(+) L44.2
+6V1: C113.1 C131.1(+) C261.1 C269.1 L35.2 L44.1 R170.1 R172.1
+12V: C114.1 C115.1 C116.1 C117.1 C118.1 C119.1 D4.2(C) F1.2 R171.1 U15.8(Vcc) U16.8(Vcc) U34.8(Vcc) X18.1
GND: C113.2 C114.2 C115.2 C116.2 C117.2 C118.2 C119.2 C120.2 C125.2(-) C128.2 C129.2 C131.2(-) C136.2 C137.2 C138.2(-) C140.2(-) C141.2(-) C143.2 C144.2 C145.2 C147.2 C148.2 C150.2 C151.2 C152.2 C153.2 C154.2 C156.2 C157.2 C158.2 C159.2 C161.2 C162.2 C163.2 C164.2 C165.2(-) C166.2(-) C167.2(-) C168.2(-) C171.2(-) C172.1 C174.1 C175.1 C176.1 C177.1 C178.1 C179.1 C180.1 C181.1 C182.1 C183.1 C184.1 C185.1 C186.1 C187.1 C188.1 C189.1 C190.1 C191.1 C192.1 C193.1 C194.1 C196.1 C197.1 C198.1 C199.1 C200.1 C201.1 C202.1 C203.1 C204.1 C205.1 C206.1 C207.1 C208.1 C209.1 C210.1 C211.1 C212.1 C213.1 C214.1 C215.1 C216.1 C217.1 C218.1 C219.1 C220.1 C221.1 C222.1 C223.1 C224.1 C225.1 C227.1 C228.1 C229.2 C230.2 C231.2 C232.2 C233.2 C234.2 C235.2 C236.2 C237.2 C238.2 C239.2 C240.2 C241.2 C242.2 C243.2 C244.2 C245.2 C246.2 C247.2 C248.2 C249.2 C250.2 C251.2 C252.2 C254.2 C255.2 C256.2 C257.2 C258.2 C259.2 C260.2 C261.2 C262.2 C263.2 C264.2 C265.2 C266.2 C268.2 C269.2 C270.2 C271.2 C272.2 C273.2 C274.2 C276.2 C277.2 C279.2 C280.2 C281.2 C282.2 C283.2 C284.2 C285.2 C286.1 C287.1 D1.2(A) D2.2(A) D3.2(A) D4.1(A) Q4.2(E) R128.1 R129.1 R131.2 R132.2 R138.2 R168.1 R169.2 U8.A1(GND) U8.A22(GND) U8.AA5(GND) U8.AA9(GND) U8.AA13(GND) U8.AA17(GND) U8.AB1(GND) U8.AB22(GND) U8.B5(GND) U8.B9(GND) U8.B13(GND) U8.B17(GND) U8.D4(GND) U8.D18(GND) U8.E2(GND) U8.E7(GND) U8.E11(GND) U8.E15(GND) U8.E21(GND) U8.G5(GND) U8.G18(GND) U8.H7(GND) U8.J2(GND) U8.J9(GND) U8.J11(GND) U8.J13(GND) U8.J15(GND) U8.J21(GND) U8.K10(GND) U8.K12(GND) U8.K14(GND) U8.L5(GND) U8.L9(GND) U8.L11(GND) U8.L13(GND) U8.L18(GND) U8.M10(GND) U8.M12(GND) U8.M14(GND) U8.N2(GND) U8.N9(GND) U8.N11(GND) U8.N13(GND) U8.N17(GND) U8.N21(GND) U8.P10(GND) U8.P12(GND) U8.P14(GND) U8.R5(GND) U8.R18(GND) U8.U2(GND) U8.U7(GND) U8.U21(GND) U8.V4(GND) U8.V10(GND) U8.V14(GND) U8.W7(GND) U8.W16(GND) U8.W19(GND) U9.0(GND_PAD) U11.5(VSS) U11.10(VSS) U11.17(VSS) U11.21(VSS) U11.26(VSS) U11.40(VSS) U11.55(VSS) U11.60(VSS) U11.67(VSS) U11.71(VSS) U11.76(VSS) U11.90(VSS) U15.0(GND) U15.3(INH) U15.7(GND) U16.0(GND) U16.7(GND) U17.1(ADJ) U34.0(GND) U34.7(GND) U35.1(GND) U35.3(HYST) X5.2 X17.2
FAN_ON: U35.4(FanOn) ; port FAN_ON
INHIBIT: Q4.3(C) U16.3(INH) U34.3(INH)
OVERHEAT: R173.2 U35.6(~{WRN}) ; port OVERHEAT
NetC120_1: C120.1 R133.2 U17.3(Vin)
NetC128_1: C128.1 C132.1 U15.4(COMP)
NetC129_1: C129.1 C133.1 U16.4(COMP)
NetC132_2: C132.2 R131.1
NetC133_2: C133.2 R132.1
NetC137_1: C137.1 C140.1(+) C143.1 C144.1 C145.1 C151.1 C152.1 C153.1 L37.2 L41.1 L42.1 L43.1 R133.1 R137.1
NetC214_2: C214.2 C236.1 C237.1 C238.1 C239.1 C240.1 C241.1 C242.1 C243.1 C244.1 C245.1 C280.1 C284.1 C285.1 C286.2 C287.2 Q3.2(C) Q3.4(C) U9.6(VDD_1V) U9.19(VDD_1V) U9.20(AVDDL_1V) U9.27(AVDDL_1V) U9.30(AVDDL_1V) U9.33(AVDDL_1V) U9.36(AVDDL_1V) U9.39(AVDDL_1V) U9.48(VDD_1V) U9.56(VDD_1V) U9.63(VDD_1V)
NetC266_1: C266.1 C267.1 U34.4(COMP)
NetC267_2: C267.2 R169.1
NetC281_1: C281.1 C282.1 C283.1 L45.2 U9.21(AVDDH_2V5) U9.31(AVDDH_2V5)
NetD1_1: D1.1(C) L36.1 U15.1(OUT)
NetD2_1: D2.1(C) L37.1 U16.1(OUT)
NetD3_1: D3.1(C) L35.1 U34.1(OUT)
NetF1_1: F1.1 X5.1
NetQ3_1: Q3.1(B) U9.47(CTRL_1V0)
NetQ4_1: Q4.1(B) R174.2 U35.5(~{OT})
NetR128_2: R128.2 R136.2 U15.5(FB)
NetR129_2: R129.2 R137.2 U16.5(FB)
NetR168_2: R168.2 R170.2 U34.5(FB)
NetR171_2: R171.2 R172.2 X17.1
NetU15_2: U15.2(SYNC) U16.2(SYNC) U34.2(SYNC)
NetU35_8: U35.8(~{FAN}-) X18.2

Not connected (* = marked no-connect by the designer): U8 AB5(NC)* E8(NC)* E10(NC)* F8(NC)* F9(NC)* F10(NC)* F12(NC)* G8(NC)* G9(NC)* G11(NC)* H10(NC)* H11(NC)* H12(NC)* R7(NC)* R8(NC)* R9(NC)* R11(NC)* R13(NC)* R15(NC)* R16(NC)* T7(NC)* T8(NC)* T10(NC)* T11(NC)* T12(NC)* T14(NC)* T15(NC)* T16(NC)* U6(NC)* U8(NC)* U9(NC)* U10(NC)* U12(NC)* U16(NC)* U17(NC)* V5(NC)* V7(NC)* V9(NC)* V13(NC)* V17(NC)* V18(NC)* V19(NC)* W6(NC)* W8(NC)* W9(NC)* W10(NC)* W13(NC)* W14(NC)* W15(NC)* W17(NC)* W18(NC)* Y5(NC)* Y6(NC)* Y8(NC)* Y10(NC)* Y14(NC)* Y16(NC)* Y18(NC)*; U9 7(NC)* 8(NC)* 9(NC)* 10(NC)* 11(NC)* 46(CTRL_2V5)*; U11 14(NC)* 16(NC)* 66(NC)*; U15 6(VREF)*; U16 6(VREF)*; U34 6(VREF)*

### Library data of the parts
C113 C120 C143-C145 C147 C148 C156-C159 C172 C174-C194 C196-C225 C227-C252 C254-C260 C262-C265 C268 C270-C274 C276 C277 C279-C282 C286 C287 = C0402: Конденсатор; Manufacturer: MURATA; Tolerance: 20%; Name: SMD0402; U/P/TKE: Y5V
C114-C116 = C2220: Конденсатор; Manufacturer: TDK; Name: C5750Y5V1H226Z; U/P/TKE: Y5V
C117-C119 = C1210_H2,5: Конденсатор; Manufacturer: TAIYO YUDEN; Tolerance: 20%; Name: UMK325 BJ106MM; U/P/TKE: X5R
C125 C138 C165-C168 C171 = CD7343: Конденсатор; Manufacturer: SPRAGUE; Name: CASE-D; U/P/TKE: 16V
C128 C129 C150-C154 C161-C164 C266 C269 = C0603: Конденсатор; Manufacturer: MURATA; Tolerance: 20%; Name: SMD0603; U/P/TKE: NP0
C131 C140 C141 = CD7343: Конденсатор; Manufacturer: Kemet; Name: CASE-D; U/P/TKE: 10V
C132 C133 C267 = C0603: Конденсатор; Manufacturer: MURATA; Tolerance: 20%; Name: SMD0603; U/P/TKE: X7R
C136 C137 C261 = C1206: Конденсатор; Manufacturer: Taiyo Yuden; Tolerance: 10%; Name: UMK316AB7475KL-T; U/P/TKE: Y5V 50V
C283-C285 = C0805: Конденсатор; Manufacturer: MURATA; Tolerance: 20%; Name: SMD0805; U/P/TKE: Y5R
D1-D3 = B3x0B: Диод Шоттки; Manufacturer: ST
D4 = STPS3L40S: Диод; Manufacturer: ST; Misc: TVS 30V 2.5kW
F1 = FUSE_PTC: FUSE PTC resetable; Manufacturer: Bel Fuse; Name: 0ZCD0185FF2C; U/P/TKE: 33V
L35-L37 = L-SRN8040: Индуктивность; Manufacturer: BOURNS
L40-L44 = TI2012_1: Дроссель ЭМС; Manufacturer: MURATA
L45 = TI160808: Дроссель ЭМС; Manufacturer: MURATA
Q3 = BCP69: Транзистор; Manufacturer: INFINEON
Q4 = BC 817: Транзистор; Manufacturer: Philips
R128 R129 R131-R133 R136-R138 R168-R174 = R0603: as R175 on sheet Total
U8 = XC6SLX75-2FGG484C: Spartan-6 LX 1.2V FPGA, 270 User I/Os, 484-Ball Fine-Pitch BGA (1.0mm Pitch), Speed Grade 2, Commercial Grade, Pb-Free; Manufacturer: Xilinx
U9 = ET1011C2-CI-DT: Микросхема; Manufacturer: LSI; PDF: d:\Proj\Components\LSI\Si5330.pdf; Misc: Gigabit Ethernet Transceiver
U11 = CY7C1354C-166AXI: Микросхема; Manufacturer: Cypress; Misc: Pipelined SRAM with NoBL™ Architecture; PDF: d:\Proj\Components\Cypress\CY7C1354C_CY7C1356C2.pdf
U15 U16 U34 = L5973D: Микросхема; Manufacturer: ST; Misc: step down switching regulator; Swap: No; PDF: d:\Proj\Components\ST\L5973D(stepdown2,5A)_ST.pdf
U17 = LD1117ADJ: Микросхема; Manufacturer: STMicro; Swap: No
U35 = MAX6665ASA: Микросхема; Manufacturer: Maxim; Swap: No; PDF: d:\Proj\Components\Maxim\MAX6665.pdf; Misc: Fan Controller/Driver
X5 = MF-2MRA: Разъем; Manufacturer: BM
X17 X18 = WF-2: Разъем; Manufacturer: BM

## Sheet FPGA_RAM.SchDoc: BaseBand Front-End
size A2; Revision: 1; SheetNumber: 2
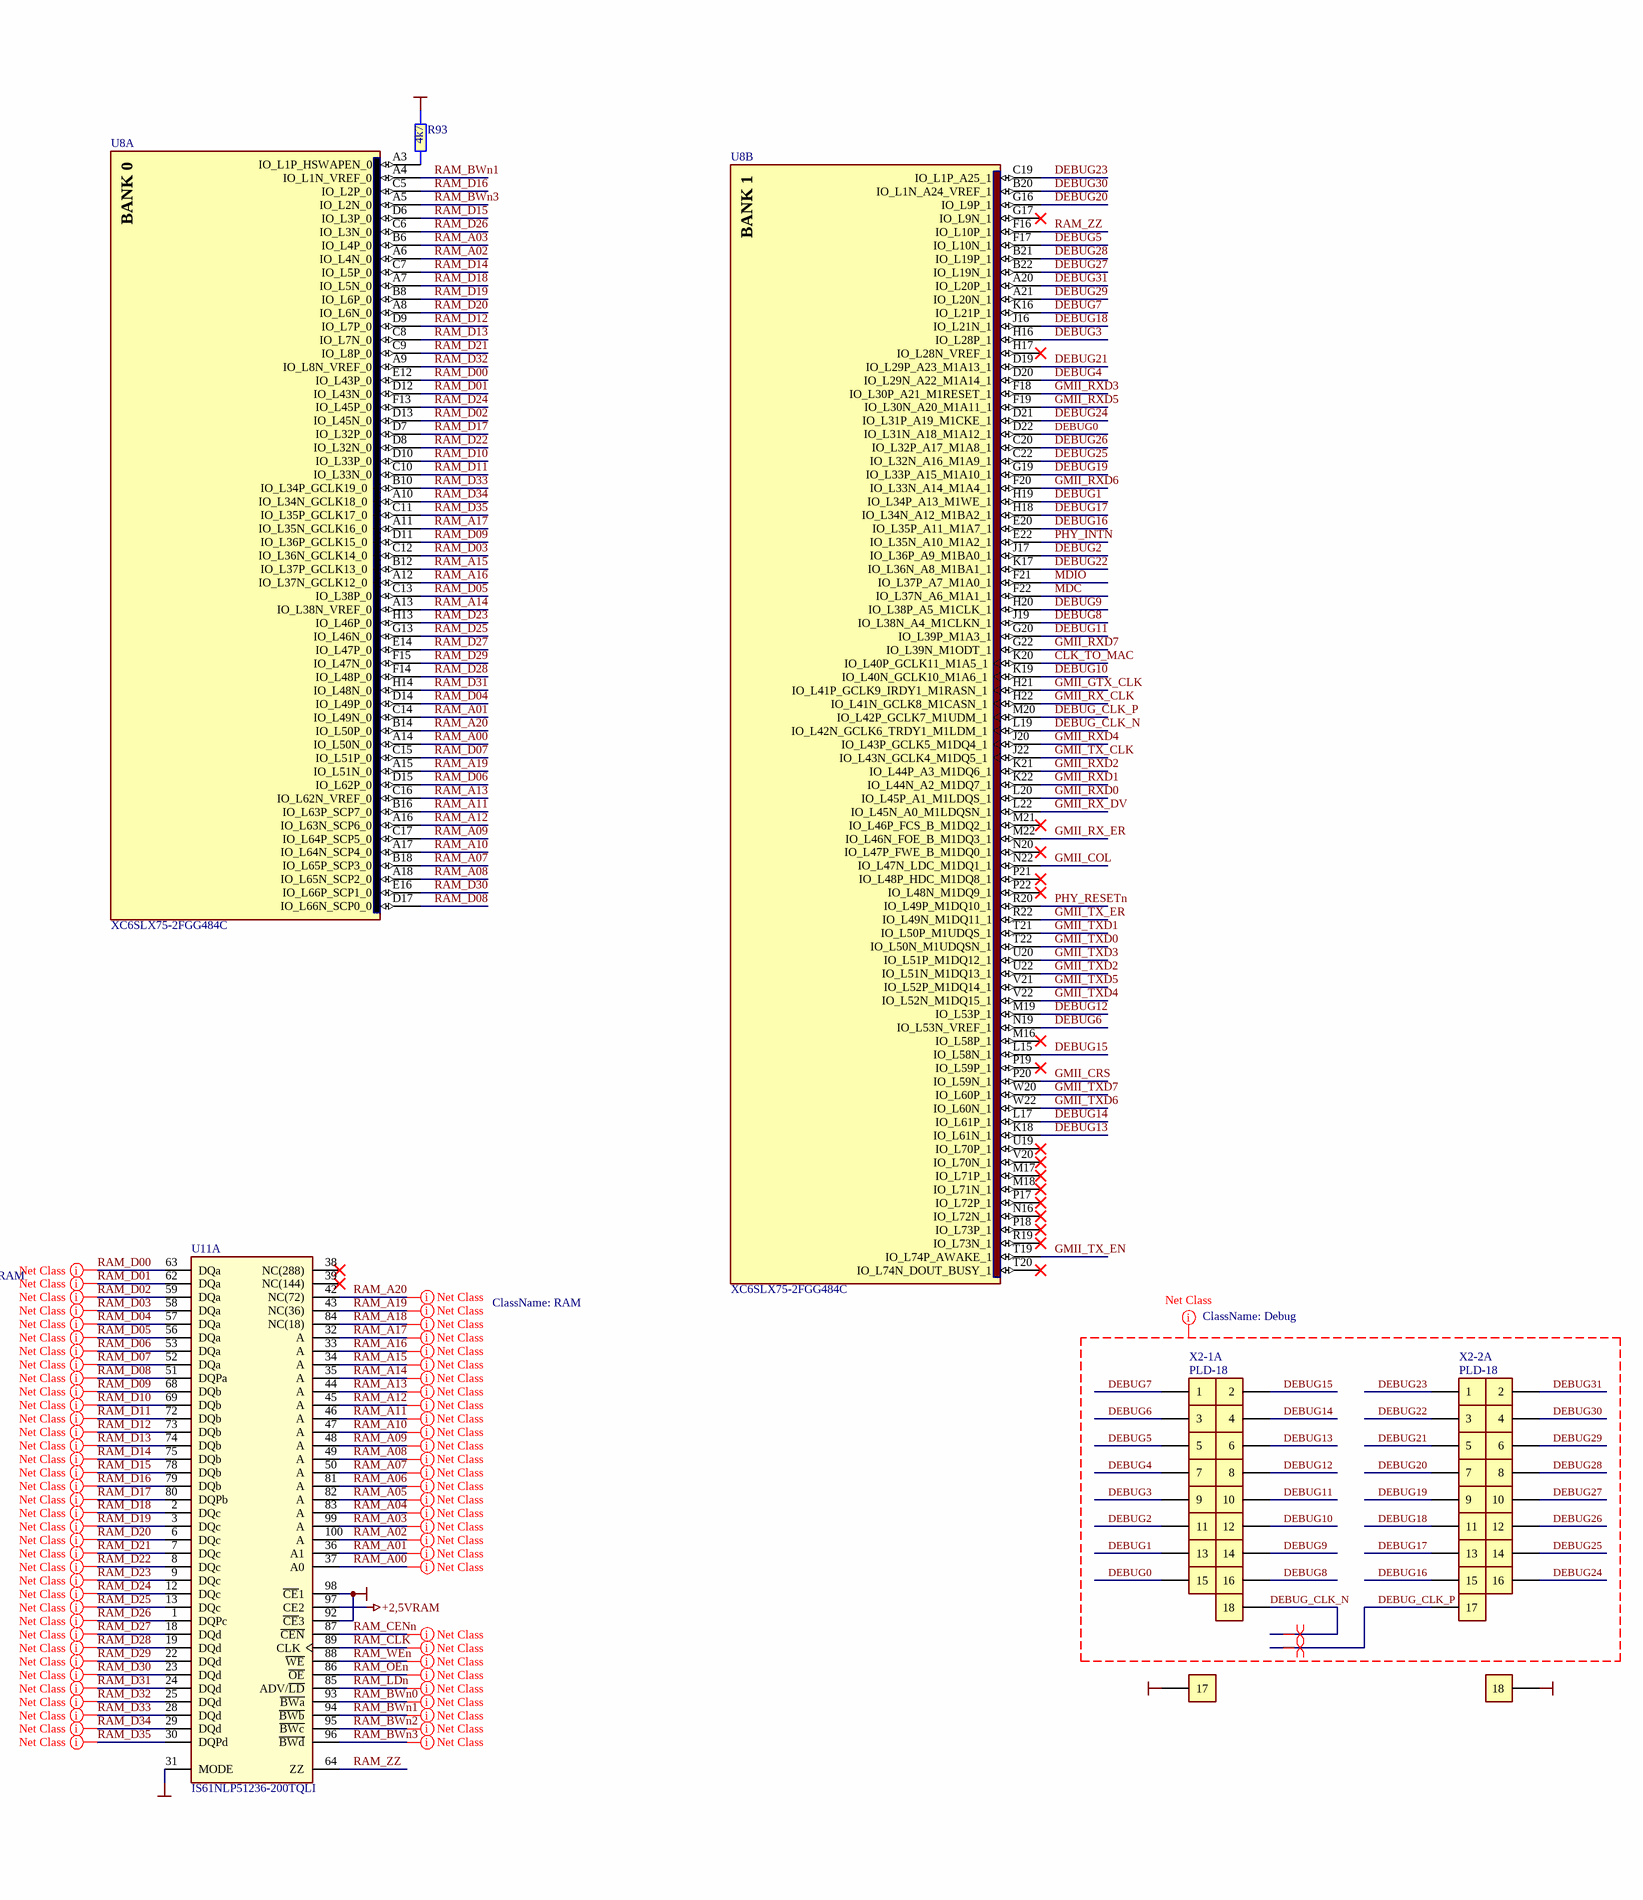
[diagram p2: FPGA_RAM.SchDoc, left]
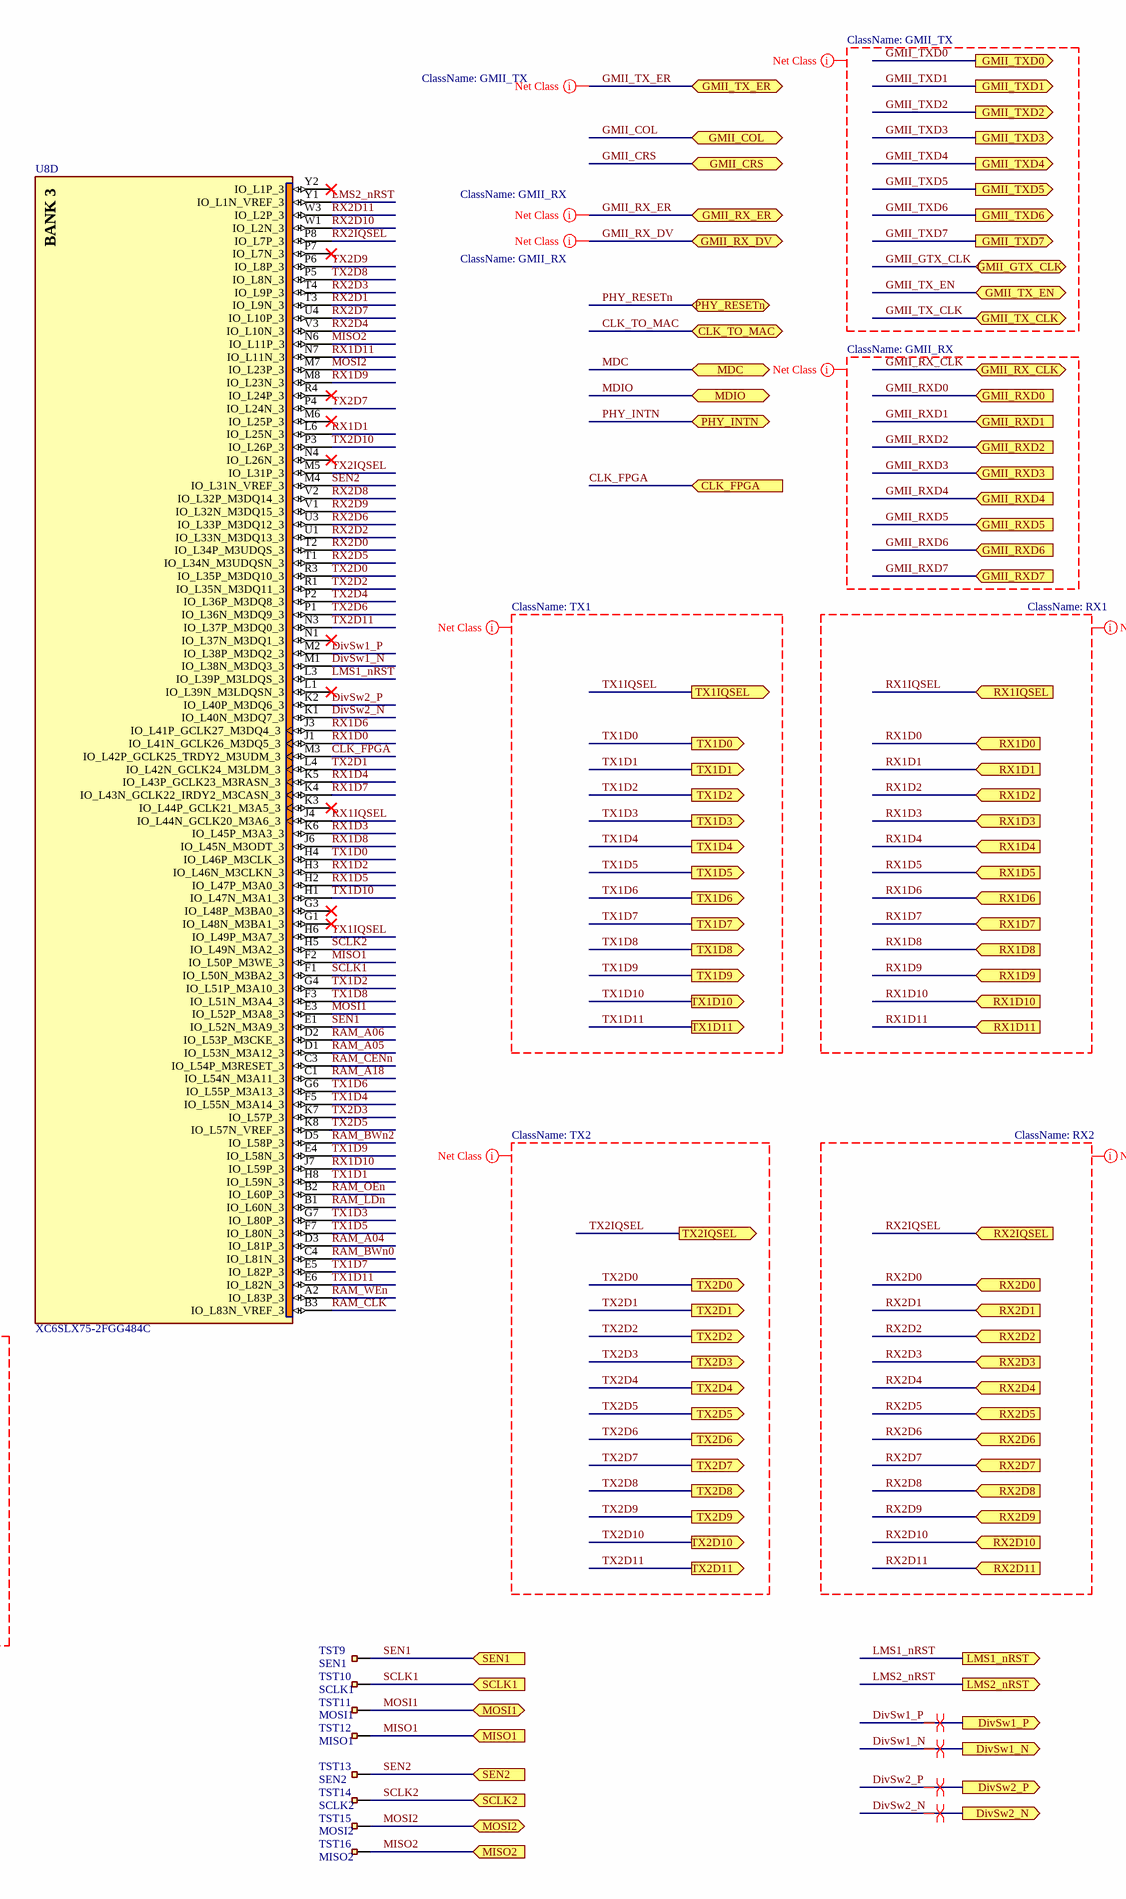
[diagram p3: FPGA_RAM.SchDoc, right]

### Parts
R93  4k7  [R0603-PHILLIPS]
TST9  SEN1  [kp40x40]
TST10  SCLK1  [kp40x40]
TST11  MOSI1  [kp40x40]
TST12  MISO1  [kp40x40]
TST13  SEN2  [kp40x40]
TST14  SCLK2  [kp40x40]
TST15  MOSI2  [kp40x40]
TST16  MISO2  [kp40x40]
U8  XC6SLX75-2FGG484C  [FBGA484]  (parts A,B,D of 8)
U11  IS61NLP51236-200TQLI  [QFP-10020X14/0.65]]  (part A of 2)
X2-1  PLD-18  [PLD-18]  (parts A,B,C,D,E,F,G,H,I,J,K,L,M,N,O,P,Q,R of 18)
X2-2  PLD-18  [PLD-18]  (parts A,B,C,D,E,F,G,H,I,J,K,L,M,N,O,P,Q,R of 18)

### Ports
CLK_FPGA (in), CLK_TO_MAC, DivSw1_N (out), DivSw1_P (out), DivSw2_N (out), DivSw2_P (out), GMII_COL, GMII_CRS, GMII_GTX_CLK, GMII_RX_CLK, GMII_RX_DV, GMII_RX_ER, GMII_RXD0 (in), GMII_RXD1 (in), GMII_RXD2 (in), GMII_RXD3 (in), GMII_RXD4 (in), GMII_RXD5 (in), GMII_RXD6 (in), GMII_RXD7 (in), GMII_TX_CLK, GMII_TX_EN, GMII_TX_ER, GMII_TXD0 (out), GMII_TXD1 (out), GMII_TXD2 (out), GMII_TXD3 (out), GMII_TXD4 (out), GMII_TXD5 (out), GMII_TXD6 (out), GMII_TXD7 (out), LMS1_nRST (out), LMS2_nRST (out), MDC, MDIO, MISO1 (in), MISO2 (in), MOSI1 (bidir), MOSI2 (bidir), PHY_INTN, PHY_RESETn, RX1D0 (in), RX1D1 (in), RX1D2 (in), RX1D3 (in), RX1D4 (in), RX1D5 (in), RX1D6 (in), RX1D7 (in), RX1D8 (in), RX1D9 (in), RX1D10 (in), RX1D11 (in), RX1IQSEL (in), RX2D0 (in), RX2D1 (in), RX2D2 (in), RX2D3 (in), RX2D4 (in), RX2D5 (in), RX2D6 (in), RX2D7 (in), RX2D8 (in), RX2D9 (in), RX2D10 (in), RX2D11 (in), RX2IQSEL (in), SCLK1 (in), SCLK2 (in), SEN1 (in), SEN2 (in), TX1D0 (out), TX1D1 (out), TX1D2 (out), TX1D3 (out), TX1D4 (out), TX1D5 (out), TX1D6 (out), TX1D7 (out), TX1D8 (out), TX1D9 (out), TX1D10 (out), TX1D11 (out), TX1IQSEL (out), TX2D0 (out), TX2D1 (out), TX2D2 (out), TX2D3 (out), TX2D4 (out), TX2D5 (out), TX2D6 (out), TX2D7 (out), TX2D8 (out), TX2D9 (out), TX2D10 (out), TX2D11 (out), TX2IQSEL (out)

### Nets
+2,5VRAM: U11.97(CE2)
GND: R93.2 U11.31(MODE) U11.92(~{CE}3) U11.98(~{CE}1) X2-1.17 X2-2.18
CLK_FPGA: U8.M3(IO_L42P_GCLK25_TRDY2_M3UDM_3) ; port CLK_FPGA
CLK_TO_MAC: U8.K20(IO_L40P_GCLK11_M1A5_1) ; port CLK_TO_MAC
DEBUG0: U8.D22(IO_L31N_A18_M1A12_1) X2-1.15
DEBUG1: U8.H19(IO_L34P_A13_M1WE_1) X2-1.13
DEBUG2: U8.J17(IO_L36P_A9_M1BA0_1) X2-1.11
DEBUG3: U8.H16(IO_L28P_1) X2-1.9
DEBUG4: U8.D20(IO_L29N_A22_M1A14_1) X2-1.7
DEBUG5: U8.F17(IO_L10N_1) X2-1.5
DEBUG6: U8.N19(IO_L53N_VREF_1) X2-1.3
DEBUG7: U8.K16(IO_L21P_1) X2-1.1
DEBUG8: U8.J19(IO_L38N_A4_M1CLKN_1) X2-1.16
DEBUG9: U8.H20(IO_L38P_A5_M1CLK_1) X2-1.14
DEBUG10: U8.K19(IO_L40N_GCLK10_M1A6_1) X2-1.12
DEBUG11: U8.G20(IO_L39P_M1A3_1) X2-1.10
DEBUG12: U8.M19(IO_L53P_1) X2-1.8
DEBUG13: U8.K18(IO_L61N_1) X2-1.6
DEBUG14: U8.L17(IO_L61P_1) X2-1.4
DEBUG15: U8.L15(IO_L58N_1) X2-1.2
DEBUG16: U8.E20(IO_L35P_A11_M1A7_1) X2-2.15
DEBUG17: U8.H18(IO_L34N_A12_M1BA2_1) X2-2.13
DEBUG18: U8.J16(IO_L21N_1) X2-2.11
DEBUG19: U8.G19(IO_L33P_A15_M1A10_1) X2-2.9
DEBUG20: U8.G16(IO_L9P_1) X2-2.7
DEBUG21: U8.D19(IO_L29P_A23_M1A13_1) X2-2.5
DEBUG22: U8.K17(IO_L36N_A8_M1BA1_1) X2-2.3
DEBUG23: U8.C19(IO_L1P_A25_1) X2-2.1
DEBUG24: U8.D21(IO_L31P_A19_M1CKE_1) X2-2.16
DEBUG25: U8.C22(IO_L32N_A16_M1A9_1) X2-2.14
DEBUG26: U8.C20(IO_L32P_A17_M1A8_1) X2-2.12
DEBUG27: U8.B22(IO_L19N_1) X2-2.10
DEBUG28: U8.B21(IO_L19P_1) X2-2.8
DEBUG29: U8.A21(IO_L20N_1) X2-2.6
DEBUG30: U8.B20(IO_L1N_A24_VREF_1) X2-2.4
DEBUG31: U8.A20(IO_L20P_1) X2-2.2
DEBUG_CLK_N: U8.L19(IO_L42N_GCLK6_TRDY1_M1LDM_1) X2-1.18
DEBUG_CLK_P: U8.M20(IO_L42P_GCLK7_M1UDM_1) X2-2.17
DivSw1_N: U8.M1(IO_L38N_M3DQ3_3) ; port DivSw1_N
DivSw1_P: U8.M2(IO_L38P_M3DQ2_3) ; port DivSw1_P
DivSw2_N: U8.K1(IO_L40N_M3DQ7_3) ; port DivSw2_N
DivSw2_P: U8.K2(IO_L40P_M3DQ6_3) ; port DivSw2_P
GMII_COL: U8.N22(IO_L47N_LDC_M1DQ1_1) ; port GMII_COL
GMII_CRS: U8.P20(IO_L59N_1) ; port GMII_CRS
GMII_GTX_CLK: U8.H21(IO_L41P_GCLK9_IRDY1_M1RASN_1) ; port GMII_GTX_CLK
GMII_RX_CLK: U8.H22(IO_L41N_GCLK8_M1CASN_1) ; port GMII_RX_CLK
GMII_RX_DV: U8.L22(IO_L45N_A0_M1LDQSN_1) ; port GMII_RX_DV
GMII_RX_ER: U8.M22(IO_L46N_FOE_B_M1DQ3_1) ; port GMII_RX_ER
GMII_RXD0: U8.L20(IO_L45P_A1_M1LDQS_1) ; port GMII_RXD0
GMII_RXD1: U8.K22(IO_L44N_A2_M1DQ7_1) ; port GMII_RXD1
GMII_RXD2: U8.K21(IO_L44P_A3_M1DQ6_1) ; port GMII_RXD2
GMII_RXD3: U8.F18(IO_L30P_A21_M1RESET_1) ; port GMII_RXD3
GMII_RXD4: U8.J20(IO_L43P_GCLK5_M1DQ4_1) ; port GMII_RXD4
GMII_RXD5: U8.F19(IO_L30N_A20_M1A11_1) ; port GMII_RXD5
GMII_RXD6: U8.F20(IO_L33N_A14_M1A4_1) ; port GMII_RXD6
GMII_RXD7: U8.G22(IO_L39N_M1ODT_1) ; port GMII_RXD7
GMII_TX_CLK: U8.J22(IO_L43N_GCLK4_M1DQ5_1) ; port GMII_TX_CLK
GMII_TX_EN: U8.T19(IO_L74P_AWAKE_1) ; port GMII_TX_EN
GMII_TX_ER: U8.R22(IO_L49N_M1DQ11_1) ; port GMII_TX_ER
GMII_TXD0: U8.T22(IO_L50N_M1UDQSN_1) ; port GMII_TXD0
GMII_TXD1: U8.T21(IO_L50P_M1UDQS_1) ; port GMII_TXD1
GMII_TXD2: U8.U22(IO_L51N_M1DQ13_1) ; port GMII_TXD2
GMII_TXD3: U8.U20(IO_L51P_M1DQ12_1) ; port GMII_TXD3
GMII_TXD4: U8.V22(IO_L52N_M1DQ15_1) ; port GMII_TXD4
GMII_TXD5: U8.V21(IO_L52P_M1DQ14_1) ; port GMII_TXD5
GMII_TXD6: U8.W22(IO_L60N_1) ; port GMII_TXD6
GMII_TXD7: U8.W20(IO_L60P_1) ; port GMII_TXD7
LMS1_nRST: U8.L3(IO_L39P_M3LDQS_3) ; port LMS1_nRST
LMS2_nRST: U8.Y1(IO_L1N_VREF_3) ; port LMS2_nRST
MDC: U8.F22(IO_L37N_A6_M1A1_1) ; port MDC
MDIO: U8.F21(IO_L37P_A7_M1A0_1) ; port MDIO
MISO1: TST12.1 U8.F2(IO_L50P_M3WE_3) ; port MISO1
MISO2: TST16.1 U8.N6(IO_L11P_3) ; port MISO2
MOSI1: TST11.1 U8.E3(IO_L52P_M3A8_3) ; port MOSI1
MOSI2: TST15.1 U8.M7(IO_L23P_3) ; port MOSI2
PHY_INTN: U8.E22(IO_L35N_A10_M1A2_1) ; port PHY_INTN
PHY_RESETn: U8.R20(IO_L49P_M1DQ10_1) ; port PHY_RESETn
RAM_A00: U8.A14(IO_L50N_0) U11.37(A0)
RAM_A01: U8.C14(IO_L49N_0) U11.36(A1)
RAM_A02: U8.A6(IO_L4N_0) U11.100(A)
RAM_A03: U8.B6(IO_L4P_0) U11.99(A)
RAM_A04: U8.D3(IO_L81P_3) U11.83(A)
RAM_A05: U8.D1(IO_L53N_M3A12_3) U11.82(A)
RAM_A06: U8.D2(IO_L53P_M3CKE_3) U11.81(A)
RAM_A07: U8.B18(IO_L65P_SCP3_0) U11.50(A)
RAM_A08: U8.A18(IO_L65N_SCP2_0) U11.49(A)
RAM_A09: U8.C17(IO_L64P_SCP5_0) U11.48(A)
RAM_A10: U8.A17(IO_L64N_SCP4_0) U11.47(A)
RAM_A11: U8.B16(IO_L63P_SCP7_0) U11.46(A)
RAM_A12: U8.A16(IO_L63N_SCP6_0) U11.45(A)
RAM_A13: U8.C16(IO_L62N_VREF_0) U11.44(A)
RAM_A14: U8.A13(IO_L38N_VREF_0) U11.35(A)
RAM_A15: U8.B12(IO_L37P_GCLK13_0) U11.34(A)
RAM_A16: U8.A12(IO_L37N_GCLK12_0) U11.33(A)
RAM_A17: U8.A11(IO_L35N_GCLK16_0) U11.32(A)
RAM_A18: U8.C1(IO_L54N_M3A11_3) U11.84(NC(18))
RAM_A19: U8.A15(IO_L51N_0) U11.43(NC(36))
RAM_A20: U8.B14(IO_L50P_0) U11.42(NC(72))
RAM_BWn0: U8.C4(IO_L81N_3) U11.93(~{BWa})
RAM_BWn1: U8.A4(IO_L1N_VREF_0) U11.94(~{BWb})
RAM_BWn2: U8.D5(IO_L58P_3) U11.95(~{BWc})
RAM_BWn3: U8.A5(IO_L2N_0) U11.96(~{BWd})
RAM_CENn: U8.C3(IO_L54P_M3RESET_3) U11.87(~{CEN})
RAM_CLK: U8.B3(IO_L83N_VREF_3) U11.89(CLK)
RAM_D00: U8.E12(IO_L43P_0) U11.63(DQa)
RAM_D01: U8.D12(IO_L43N_0) U11.62(DQa)
RAM_D02: U8.D13(IO_L45N_0) U11.59(DQa)
RAM_D03: U8.C12(IO_L36N_GCLK14_0) U11.58(DQa)
RAM_D04: U8.D14(IO_L49P_0) U11.57(DQa)
RAM_D05: U8.C13(IO_L38P_0) U11.56(DQa)
RAM_D06: U8.D15(IO_L62P_0) U11.53(DQa)
RAM_D07: U8.C15(IO_L51P_0) U11.52(DQa)
RAM_D08: U8.D17(IO_L66N_SCP0_0) U11.51(DQPa)
RAM_D09: U8.D11(IO_L36P_GCLK15_0) U11.68(DQb)
RAM_D10: U8.D10(IO_L33P_0) U11.69(DQb)
RAM_D11: U8.C10(IO_L33N_0) U11.72(DQb)
RAM_D12: U8.D9(IO_L7P_0) U11.73(DQb)
RAM_D13: U8.C8(IO_L7N_0) U11.74(DQb)
RAM_D14: U8.C7(IO_L5P_0) U11.75(DQb)
RAM_D15: U8.D6(IO_L3P_0) U11.78(DQb)
RAM_D16: U8.C5(IO_L2P_0) U11.79(DQb)
RAM_D17: U8.D7(IO_L32P_0) U11.80(DQPb)
RAM_D18: U8.A7(IO_L5N_0) U11.2(DQc)
RAM_D19: U8.B8(IO_L6P_0) U11.3(DQc)
RAM_D20: U8.A8(IO_L6N_0) U11.6(DQc)
RAM_D21: U8.C9(IO_L8P_0) U11.7(DQc)
RAM_D22: U8.D8(IO_L32N_0) U11.8(DQc)
RAM_D23: U8.H13(IO_L46P_0) U11.9(DQc)
RAM_D24: U8.F13(IO_L45P_0) U11.12(DQc)
RAM_D25: U8.G13(IO_L46N_0) U11.13(DQc)
RAM_D26: U8.C6(IO_L3N_0) U11.1(DQPc)
RAM_D27: U8.E14(IO_L47P_0) U11.18(DQd)
RAM_D28: U8.F14(IO_L48P_0) U11.19(DQd)
RAM_D29: U8.F15(IO_L47N_0) U11.22(DQd)
RAM_D30: U8.E16(IO_L66P_SCP1_0) U11.23(DQd)
RAM_D31: U8.H14(IO_L48N_0) U11.24(DQd)
RAM_D32: U8.A9(IO_L8N_VREF_0) U11.25(DQd)
RAM_D33: U8.B10(IO_L34P_GCLK19_0) U11.28(DQd)
RAM_D34: U8.A10(IO_L34N_GCLK18_0) U11.29(DQd)
RAM_D35: U8.C11(IO_L35P_GCLK17_0) U11.30(DQPd)
RAM_LDn: U8.B1(IO_L60N_3) U11.85(ADV/~{LD})
RAM_OEn: U8.B2(IO_L60P_3) U11.86(~{OE})
RAM_WEn: U8.A2(IO_L83P_3) U11.88(~{WE})
RAM_ZZ: U8.F16(IO_L10P_1) U11.64(ZZ)
RX1D0: U8.J1(IO_L41N_GCLK26_M3DQ5_3) ; port RX1D0
RX1D1: U8.L6(IO_L25N_3) ; port RX1D1
RX1D2: U8.H3(IO_L46N_M3CLKN_3) ; port RX1D2
RX1D3: U8.K6(IO_L45P_M3A3_3) ; port RX1D3
RX1D4: U8.K5(IO_L43P_GCLK23_M3RASN_3) ; port RX1D4
RX1D5: U8.H2(IO_L47P_M3A0_3) ; port RX1D5
RX1D6: U8.J3(IO_L41P_GCLK27_M3DQ4_3) ; port RX1D6
RX1D7: U8.K4(IO_L43N_GCLK22_IRDY2_M3CASN_3) ; port RX1D7
RX1D8: U8.J6(IO_L45N_M3ODT_3) ; port RX1D8
RX1D9: U8.M8(IO_L23N_3) ; port RX1D9
RX1D10: U8.J7(IO_L59P_3) ; port RX1D10
RX1D11: U8.N7(IO_L11N_3) ; port RX1D11
RX1IQSEL: U8.J4(IO_L44N_GCLK20_M3A6_3) ; port RX1IQSEL
RX2D0: U8.T2(IO_L34P_M3UDQS_3) ; port RX2D0
RX2D1: U8.T3(IO_L9N_3) ; port RX2D1
RX2D2: U8.U1(IO_L33N_M3DQ13_3) ; port RX2D2
RX2D3: U8.T4(IO_L9P_3) ; port RX2D3
RX2D4: U8.V3(IO_L10N_3) ; port RX2D4
RX2D5: U8.T1(IO_L34N_M3UDQSN_3) ; port RX2D5
RX2D6: U8.U3(IO_L33P_M3DQ12_3) ; port RX2D6
RX2D7: U8.U4(IO_L10P_3) ; port RX2D7
RX2D8: U8.V2(IO_L32P_M3DQ14_3) ; port RX2D8
RX2D9: U8.V1(IO_L32N_M3DQ15_3) ; port RX2D9
RX2D10: U8.W1(IO_L2N_3) ; port RX2D10
RX2D11: U8.W3(IO_L2P_3) ; port RX2D11
RX2IQSEL: U8.P8(IO_L7P_3) ; port RX2IQSEL
SCLK1: TST10.1 U8.F1(IO_L50N_M3BA2_3) ; port SCLK1
SCLK2: TST14.1 U8.H5(IO_L49N_M3A2_3) ; port SCLK2
SEN1: TST9.1 U8.E1(IO_L52N_M3A9_3) ; port SEN1
SEN2: TST13.1 U8.M4(IO_L31N_VREF_3) ; port SEN2
TX1D0: U8.H4(IO_L46P_M3CLK_3) ; port TX1D0
TX1D1: U8.H8(IO_L59N_3) ; port TX1D1
TX1D2: U8.G4(IO_L51P_M3A10_3) ; port TX1D2
TX1D3: U8.G7(IO_L80P_3) ; port TX1D3
TX1D4: U8.F5(IO_L55N_M3A14_3) ; port TX1D4
TX1D5: U8.F7(IO_L80N_3) ; port TX1D5
TX1D6: U8.G6(IO_L55P_M3A13_3) ; port TX1D6
TX1D7: U8.E5(IO_L82P_3) ; port TX1D7
TX1D8: U8.F3(IO_L51N_M3A4_3) ; port TX1D8
TX1D9: U8.E4(IO_L58N_3) ; port TX1D9
TX1D10: U8.H1(IO_L47N_M3A1_3) ; port TX1D10
TX1D11: U8.E6(IO_L82N_3) ; port TX1D11
TX1IQSEL: U8.H6(IO_L49P_M3A7_3) ; port TX1IQSEL
TX2D0: U8.R3(IO_L35P_M3DQ10_3) ; port TX2D0
TX2D1: U8.L4(IO_L42N_GCLK24_M3LDM_3) ; port TX2D1
TX2D2: U8.R1(IO_L35N_M3DQ11_3) ; port TX2D2
TX2D3: U8.K7(IO_L57P_3) ; port TX2D3
TX2D4: U8.P2(IO_L36P_M3DQ8_3) ; port TX2D4
TX2D5: U8.K8(IO_L57N_VREF_3) ; port TX2D5
TX2D6: U8.P1(IO_L36N_M3DQ9_3) ; port TX2D6
TX2D7: U8.P4(IO_L24N_3) ; port TX2D7
TX2D8: U8.P5(IO_L8N_3) ; port TX2D8
TX2D9: U8.P6(IO_L8P_3) ; port TX2D9
TX2D10: U8.P3(IO_L26P_3) ; port TX2D10
TX2D11: U8.N3(IO_L37P_M3DQ0_3) ; port TX2D11
TX2IQSEL: U8.M5(IO_L31P_3) ; port TX2IQSEL
NetR93_1: R93.1 U8.A3(IO_L1P_HSWAPEN_0)

Not connected (* = marked no-connect by the designer): U8 G1(IO_L48N_M3BA1_3)* G3(IO_L48P_M3BA0_3)* G17(IO_L9N_1)* H17(IO_L28N_VREF_1)* K3(IO_L44P_GCLK21_M3A5_3)* L1(IO_L39N_M3LDQSN_3)* M6(IO_L25P_3)* M16(IO_L58P_1)* M17(IO_L71P_1)* M18(IO_L71N_1)* M21(IO_L46P_FCS_B_M1DQ2_1)* N1(IO_L37N_M3DQ1_3)* N4(IO_L26N_3)* N16(IO_L72N_1)* N20(IO_L47P_FWE_B_M1DQ0_1)* P7(IO_L7N_3)* P17(IO_L72P_1)* P18(IO_L73P_1)* P19(IO_L59P_1)* P21(IO_L48P_HDC_M1DQ8_1)* P22(IO_L48N_M1DQ9_1)* R4(IO_L24P_3)* R19(IO_L73N_1)* T20(IO_L74N_DOUT_BUSY_1)* U19(IO_L70P_1)* V20(IO_L70N_1)* Y2(IO_L1P_3)*; U11 38(NC(288))* 39(NC(144))*

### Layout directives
net class RX1: RX1D0, RX1D1, RX1D2, RX1D3, RX1D4, RX1D5, RX1D6, RX1D7, RX1D8, RX1D9, RX1D10, RX1D11, RX1IQSEL
net class RX2: RX2D0, RX2D1, RX2D2, RX2D3, RX2D4, RX2D5, RX2D6, RX2D7, RX2D8, RX2D9, RX2D10, RX2D11, RX2IQSEL
net class TX1: TX1D0, TX1D1, TX1D2, TX1D3, TX1D4, TX1D5, TX1D6, TX1D7, TX1D8, TX1D9, TX1D10, TX1D11, TX1IQSEL
net class TX2: TX2D0, TX2D1, TX2D2, TX2D3, TX2D4, TX2D5, TX2D6, TX2D7, TX2D8, TX2D9, TX2D10, TX2D11, TX2IQSEL
net class GMII_TX: GMII_GTX_CLK, GMII_TX_CLK, GMII_TX_EN, GMII_TX_ER, GMII_TXD0, GMII_TXD1, GMII_TXD2, GMII_TXD3, GMII_TXD4, GMII_TXD5, GMII_TXD6, GMII_TXD7
net class RAM: RAM_A00, RAM_A01, RAM_A02, RAM_A03, RAM_A04, RAM_A05, RAM_A06, RAM_A07, RAM_A08, RAM_A09, RAM_A10, RAM_A11, RAM_A12, RAM_A13, RAM_A14, RAM_A15, RAM_A16, RAM_A17, RAM_A18, RAM_A19, RAM_A20, RAM_BWn0, RAM_BWn1, RAM_BWn2, RAM_BWn3, RAM_CENn, RAM_CLK, RAM_D00, RAM_D01, RAM_D02, RAM_D03, RAM_D04, RAM_D05, RAM_D06, RAM_D07, RAM_D08, RAM_D09, RAM_D10, RAM_D11, RAM_D12, RAM_D13, RAM_D14, RAM_D15, RAM_D16, RAM_D17, RAM_D18, RAM_D19, RAM_D20, RAM_D21, RAM_D22, RAM_D23, RAM_D24, RAM_D25, RAM_D26, RAM_D27, RAM_D28, RAM_D29, RAM_D30, RAM_D31, RAM_D32, RAM_D33, RAM_D34, RAM_D35, RAM_LDn, RAM_OEn, RAM_WEn
differential pair: DEBUG_CLK_N, DEBUG_CLK_P, DivSw1_N, DivSw1_P, DivSw2_N, DivSw2_P
net class GMII_RX: GMII_RX_CLK, GMII_RX_DV, GMII_RX_ER, GMII_RXD0, GMII_RXD1, GMII_RXD2, GMII_RXD3, GMII_RXD4, GMII_RXD5, GMII_RXD6, GMII_RXD7
net class Debug: DEBUG0, DEBUG1, DEBUG2, DEBUG3, DEBUG4, DEBUG5, DEBUG6, DEBUG7, DEBUG8, DEBUG9, DEBUG10, DEBUG11, DEBUG12, DEBUG13, DEBUG14, DEBUG15, DEBUG16, DEBUG17, DEBUG18, DEBUG19, DEBUG20, DEBUG21, DEBUG22, DEBUG23, DEBUG24, DEBUG25, DEBUG26, DEBUG27, DEBUG28, DEBUG29, DEBUG30, DEBUG31, DEBUG_CLK_N, DEBUG_CLK_P

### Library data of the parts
R93 = R0603: as R175 on sheet Total
TST9-TST16 = KP: Контактная площадка; Manufacturer: Конструктив
U8 = XC6SLX75-2FGG484C: as U8 on sheet PwrAndBias
U11 = CY7C1354C-166AXI: Микросхема; Manufacturer: ISSI; Misc: Pipelined SRAM with NoBL™ Architecture
X2-1 X2-2 = PLD-18: Разъем; Manufacturer: BM

## Sheet GBEthernet.SchDoc: BaseBand Front-End
size A3; Revision: 1; SheetNumber: 6
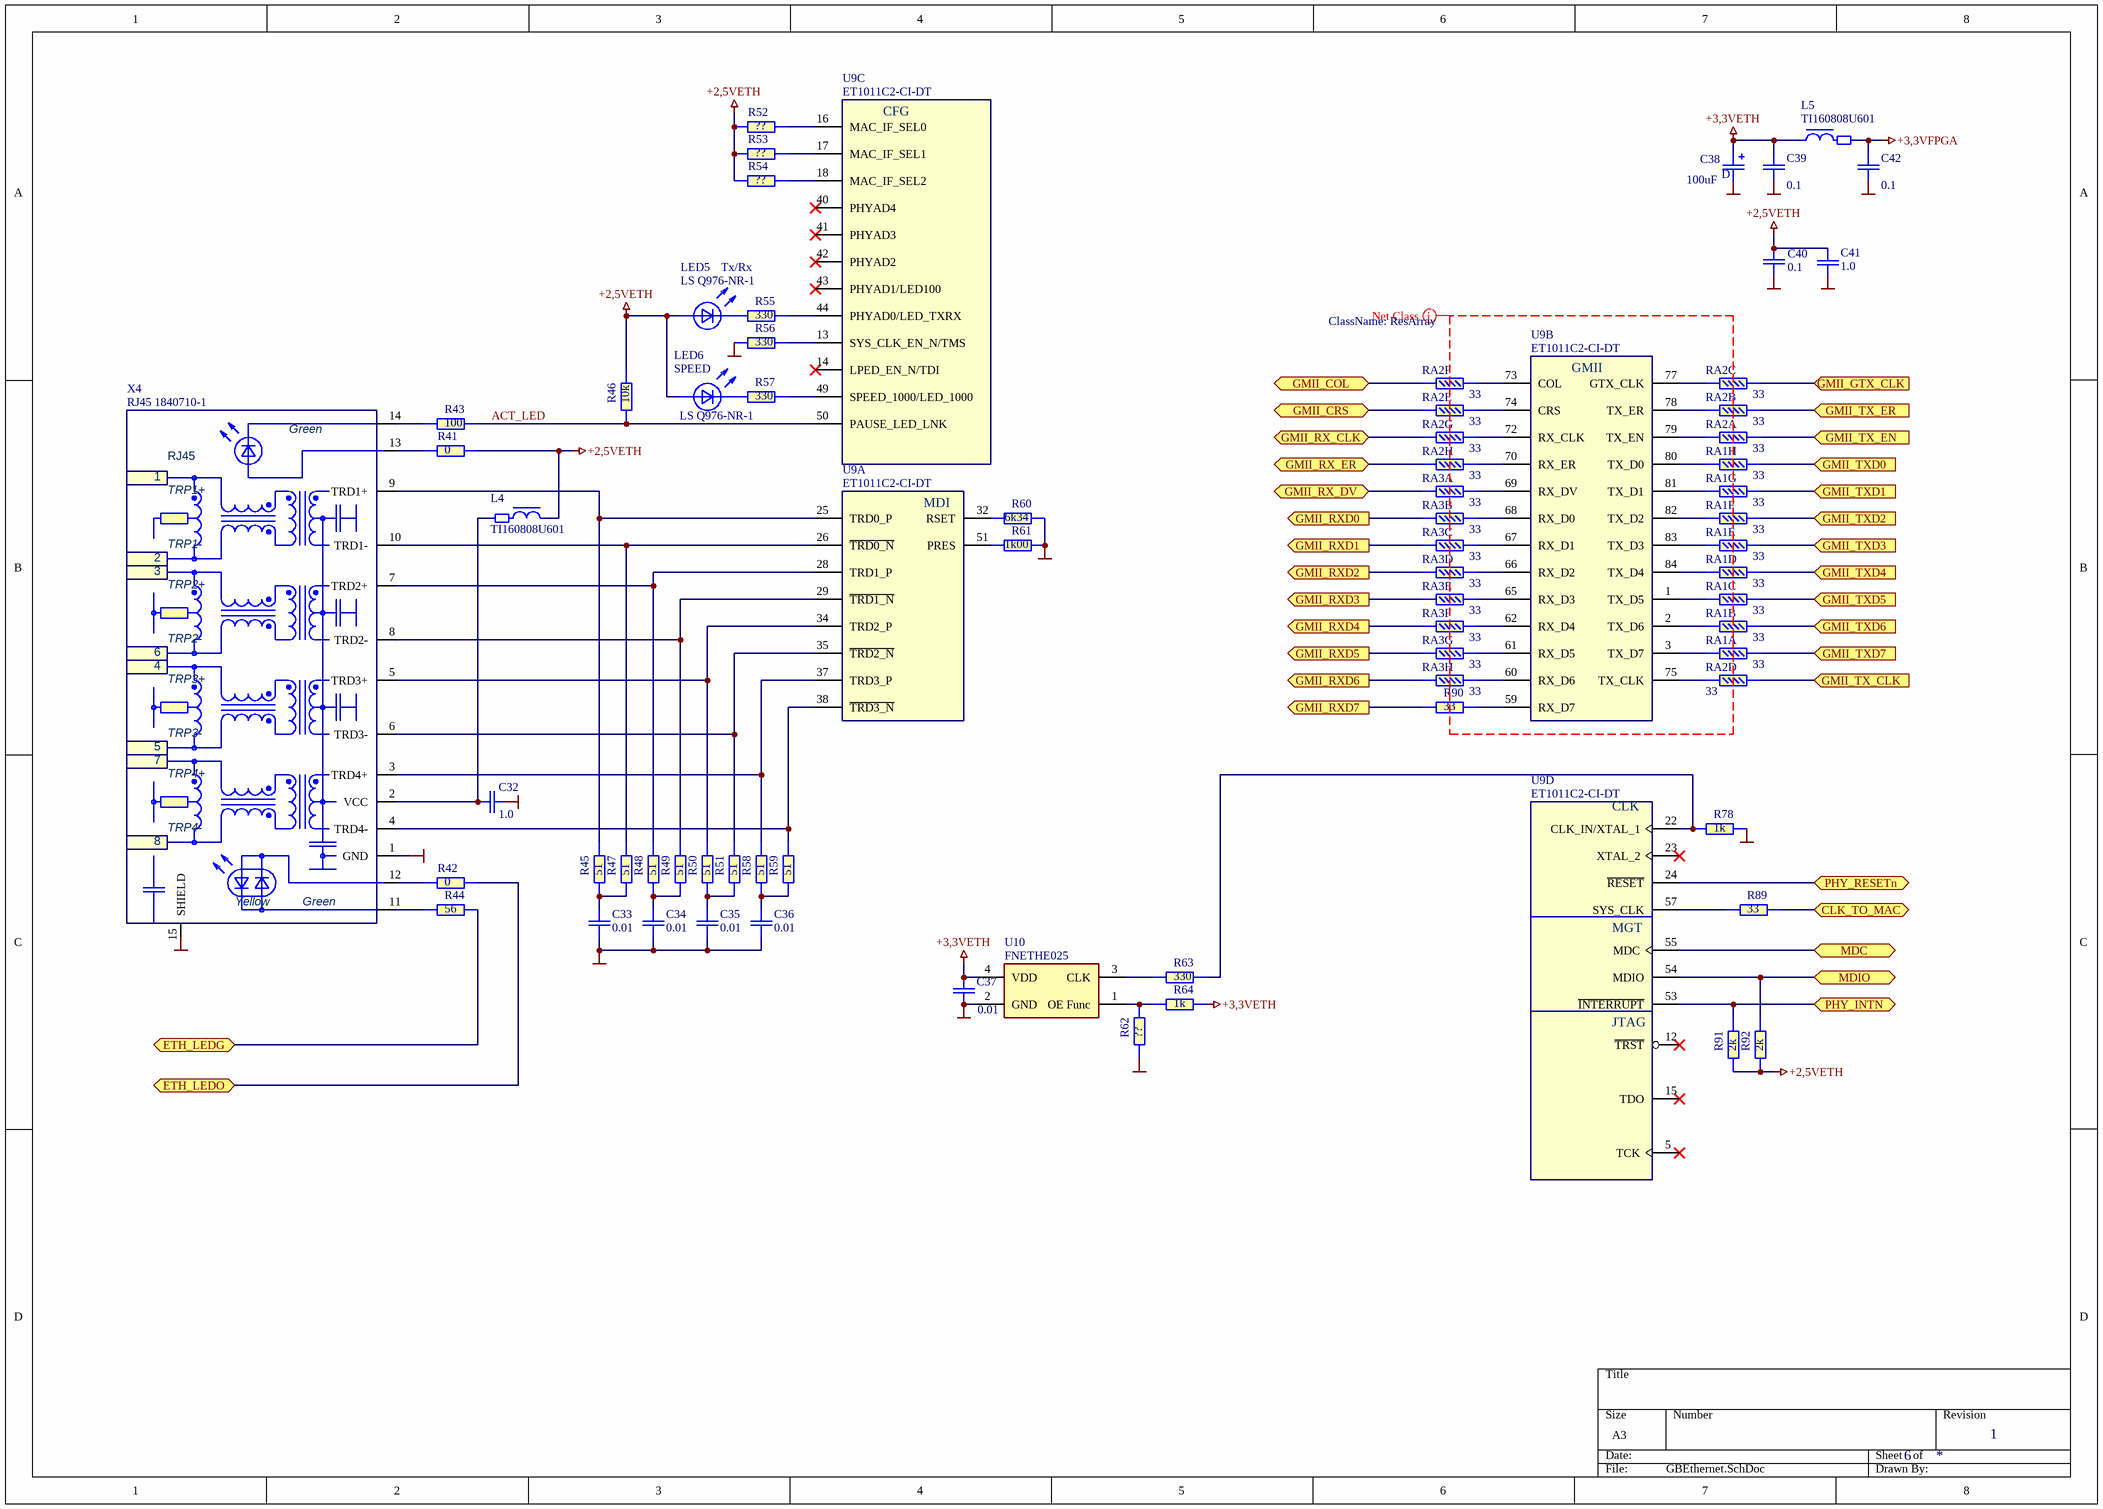
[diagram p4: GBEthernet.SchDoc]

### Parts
C32  1.0  [C0603-PHILLIPS]
C33  0.01  [C0402-Phillips]
C34  0.01  [C0402-Phillips]
C35  0.01  [C0402-Phillips]
C36  0.01  [C0402-Phillips]
C37  0.01  [C0402-Phillips]
C38  100uF  [cd7343]
C39  0.1  [C0402-Phillips]
C40  0.1  [C0402-Phillips]
C41  1.0  [C0603-PHILLIPS]
C42  0.1  [C0402-Phillips]
L4  TI160808U601  [Ti160808-Phillips]
L5  TI160808U601  [Ti160808-Phillips]
LED5  LS Q976-NR-1  Misc: Tx/Rx  [LED-0603y]
LED6  LS Q976-NR-1  Misc: SPEED  [LED-0603y]
R41  0  [R0603-PHILLIPS]
R42  0  [R0603-PHILLIPS]
R43  100  [R0603-PHILLIPS]
R44  56  [R0603-PHILLIPS]
R45  51  [R0603-PHILLIPS]
R46  10k  [R0603-PHILLIPS]
R47  51  [R0603-PHILLIPS]
R48  51  [R0603-PHILLIPS]
R49  51  [R0603-PHILLIPS]
R50  51  [R0603-PHILLIPS]
R51  51  [R0603-PHILLIPS]
R52  ??  [R0603-PHILLIPS]
R53  ??  [R0603-PHILLIPS]
R54  ??  [R0603-PHILLIPS]
R55  330  [R0603-PHILLIPS]
R56  330  [R0603-PHILLIPS]
R57  330  [R0603-PHILLIPS]
R58  51  [R0603-PHILLIPS]
R59  51  [R0603-PHILLIPS]
R60  6k34  [R0603-PHILLIPS]
R61  1k00  [R0603-PHILLIPS]
R62  ??  [R0603-PHILLIPS]
R63  330  [R0603-PHILLIPS]
R64  1k  [R0603-PHILLIPS]
R78  1k  [R0603-PHILLIPS]
R89  33  [R0603-PHILLIPS]
R90  33  [R0603-PHILLIPS]
R91  2k  [R0603-PHILLIPS]
R92  2k  [R0603-PHILLIPS]
RA1  33  [YC248]  (parts A,B,C,D,E,F,G,H of 8)
RA2  33  [YC248]  (parts A,B,C,D,E,F,G,H of 8)
RA3  33  [YC248]  (parts A,B,C,D,E,F,G,H of 8)
U9  ET1011C2-CI-DT  [QFN-84(10x10/0/4mm)with_pad]  (parts A,B,C,D of 5)
U10  FNETHE025  [7x5mm]
X4  RJ45 1840710-1  [RJ45 1840710-x]

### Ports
CLK_TO_MAC, ETH_LEDG, ETH_LEDO, GMII_COL, GMII_CRS, GMII_GTX_CLK (in), GMII_RX_CLK, GMII_RX_DV, GMII_RX_ER, GMII_RXD0 (out), GMII_RXD1 (out), GMII_RXD2 (out), GMII_RXD3 (out), GMII_RXD4 (out), GMII_RXD5 (out), GMII_RXD6 (out), GMII_RXD7 (out), GMII_TX_CLK (in), GMII_TX_EN (in), GMII_TX_ER (in), GMII_TXD0 (in), GMII_TXD1 (in), GMII_TXD2 (in), GMII_TXD3 (in), GMII_TXD4 (in), GMII_TXD5 (in), GMII_TXD6 (in), GMII_TXD7 (in), MDC, MDIO, PHY_INTN, PHY_RESETn

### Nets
+2,5VETH: C40.1 C41.2 L4.1 LED5.2(A) LED6.2(A) R41.2 R46.2 R52.1 R53.1 R54.1 R91.1 R92.1
+3,3VETH: C37.1 C38.1(+) C39.1 L5.1 R64.2 U10.4(VDD)
+3,3VFPGA: C42.1 L5.2
GND: C32.1 C33.2 C34.2 C35.2 C36.2 C37.2 C38.2(-) C39.2 C40.2 C41.1 C42.2 R56.1 R60.2 R61.2 R62.1 R78.2 U10.2(GND) X4.1(GND) X4.15(SHIELD)
ACT_LED: R43.2 R46.1 U9.50(PAUSE_LED_LNK)
CLK_TO_MAC: R89.2 ; port CLK_TO_MAC
ETH_LEDG: R44.2 ; port ETH_LEDG
ETH_LEDO: R42.2 ; port ETH_LEDO
GMII_COL: RA2.11 ; port GMII_COL
GMII_CRS: RA2.12 ; port GMII_CRS
GMII_GTX_CLK: RA2.14 ; port GMII_GTX_CLK
GMII_RX_CLK: RA2.10 ; port GMII_RX_CLK
GMII_RX_DV: RA3.16 ; port GMII_RX_DV
GMII_RX_ER: RA2.9 ; port GMII_RX_ER
GMII_RXD0: RA3.15 ; port GMII_RXD0
GMII_RXD1: RA3.14 ; port GMII_RXD1
GMII_RXD2: RA3.13 ; port GMII_RXD2
GMII_RXD3: RA3.12 ; port GMII_RXD3
GMII_RXD4: RA3.11 ; port GMII_RXD4
GMII_RXD5: RA3.10 ; port GMII_RXD5
GMII_RXD6: RA3.9 ; port GMII_RXD6
GMII_RXD7: R90.1 ; port GMII_RXD7
GMII_TX_CLK: RA2.13 ; port GMII_TX_CLK
GMII_TX_EN: RA2.16 ; port GMII_TX_EN
GMII_TX_ER: RA2.15 ; port GMII_TX_ER
GMII_TXD0: RA1.9 ; port GMII_TXD0
GMII_TXD1: RA1.10 ; port GMII_TXD1
GMII_TXD2: RA1.11 ; port GMII_TXD2
GMII_TXD3: RA1.12 ; port GMII_TXD3
GMII_TXD4: RA1.13 ; port GMII_TXD4
GMII_TXD5: RA1.14 ; port GMII_TXD5
GMII_TXD6: RA1.15 ; port GMII_TXD6
GMII_TXD7: RA1.16 ; port GMII_TXD7
MDC: U9.55(MDC) ; port MDC
MDIO: R92.2 U9.54(MDIO) ; port MDIO
PHY_INTN: R91.2 U9.53(~{INTERRUPT}) ; port PHY_INTN
PHY_RESETn: U9.24(~{RESET}) ; port PHY_RESETn
NetC32_2: C32.2 L4.2 X4.2(VCC)
NetC33_1: C33.1 R45.1 R47.1
NetC34_1: C34.1 R48.1 R49.1
NetC35_1: C35.1 R50.1 R51.1
NetC36_1: C36.1 R58.1 R59.1
NetLED5_1: LED5.1(K) R55.1
NetLED6_1: LED6.1(K) R57.1
NetR41_1: R41.1 X4.13(LED1+)
NetR42_1: R42.1 X4.12(LED2+Y)
NetR43_1: R43.1 X4.14(LED1-)
NetR44_1: R44.1 X4.11(LED2+G)
NetR45_2: R45.2 U9.25(TRD0_P) X4.9(TRD1+)
NetR47_2: R47.2 U9.26(~{TRD0_N}) X4.10(TRD1-)
NetR48_2: R48.2 U9.28(TRD1_P) X4.7(TRD2+)
NetR49_2: R49.2 U9.29(~{TRD1_N}) X4.8(TRD2-)
NetR50_2: R50.2 U9.34(TRD2_P) X4.5(TRD3+)
NetR51_2: R51.2 U9.35(~{TRD2_N}) X4.6(TRD3-)
NetR52_2: R52.2 U9.16(MAC_IF_SEL0)
NetR53_2: R53.2 U9.17(MAC_IF_SEL1)
NetR54_2: R54.2 U9.18(MAC_IF_SEL2)
NetR55_2: R55.2 U9.44(PHYAD0/LED_TXRX)
NetR56_2: R56.2 U9.13(SYS_CLK_EN_N/TMS)
NetR57_2: R57.2 U9.49(SPEED_1000/LED_1000)
NetR58_2: R58.2 U9.37(TRD3_P) X4.3(TRD4+)
NetR59_2: R59.2 U9.38(~{TRD3_N}) X4.4(TRD4-)
NetR60_1: R60.1 U9.32(RSET)
NetR61_1: R61.1 U9.51(PRES)
NetR62_2: R62.2 R64.1 U10.1(OE_Func)
NetR63_1: R63.1 U10.3(CLK)
NetR63_2: R63.2 R78.1 U9.22(CLK_IN/XTAL_1)
NetR89_1: R89.1 U9.57(SYS_CLK)
NetR90_2: R90.2 U9.59(RX_D7)
NetRA1_1: RA1.1 U9.3(TX_D7)
NetRA1_2: RA1.2 U9.2(TX_D6)
NetRA1_3: RA1.3 U9.1(TX_D5)
NetRA1_4: RA1.4 U9.84(TX_D4)
NetRA1_5: RA1.5 U9.83(TX_D3)
NetRA1_6: RA1.6 U9.82(TX_D2)
NetRA1_7: RA1.7 U9.81(TX_D1)
NetRA1_8: RA1.8 U9.80(TX_D0)
NetRA2_1: RA2.1 U9.79(TX_EN)
NetRA2_2: RA2.2 U9.78(TX_ER)
NetRA2_3: RA2.3 U9.77(GTX_CLK)
NetRA2_4: RA2.4 U9.75(TX_CLK)
NetRA2_5: RA2.5 U9.74(CRS)
NetRA2_6: RA2.6 U9.73(COL)
NetRA2_7: RA2.7 U9.72(RX_CLK)
NetRA2_8: RA2.8 U9.70(RX_ER)
NetRA3_1: RA3.1 U9.69(RX_DV)
NetRA3_2: RA3.2 U9.68(RX_D0)
NetRA3_3: RA3.3 U9.67(RX_D1)
NetRA3_4: RA3.4 U9.66(RX_D2)
NetRA3_5: RA3.5 U9.65(RX_D3)
NetRA3_6: RA3.6 U9.62(RX_D4)
NetRA3_7: RA3.7 U9.61(RX_D5)
NetRA3_8: RA3.8 U9.60(RX_D6)

Not connected (* = marked no-connect by the designer): U9 5(TCK)* 12(~{TRST})* 14(LPED_EN_N/TDI)* 15(TDO)* 23(XTAL_2)* 40(PHYAD4)* 41(PHYAD3)* 42(PHYAD2)* 43(PHYAD1/LED100)*

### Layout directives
net class ResArray: (no net found under the mark)

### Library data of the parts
C32 C41 = C0603: Конденсатор; Manufacturer: MURATA; Tolerance: 20%; Name: SMD0603; U/P/TKE: Y5V
C33-C37 C39 C40 C42 = C0402: as C113 on sheet PwrAndBias
C38 = CD7343: Конденсатор; Manufacturer: SPRAGUE; Name: CASE-G; U/P/TKE: 16V
L4 L5 = TI160808: Дроссель ЭМС; Manufacturer: MURATA
LED5 LED6 = LED0603: Светодиод; Manufacturer: OSRAM Opto Semiconductors Inc
R41-R59 R62-R64 R78 R89-R92 = R0603: as R175 on sheet Total
R60 R61 = R0603: Резистор; Manufacturer: YAGEO; Tolerance: 1%; Name: SMD0603; U/P/TKE: 0.1W
RA1-RA3 = YC248: Резисторная сборка; Manufacturer: Yageo; Misc: Резисторная сборка 8 шт. шаг 0.5 мм; U/P/TKE: 0.062W; Tolerance: 5%
U9 = ET1011C2-CI-DT: as U9 on sheet PwrAndBias
U10 = FNETHE025: Генератор; Manufacturer: Saronix-eCera; Swap: No; PDF: d:\Proj\Components\Разное\FNETHE025.pdf; Misc: Low-Jitter 25MHz Gbe XO
X4 = RJ45 1840710-5: Модуль разъёма RJ45; Manufacturer: Tyco Electronics AMP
